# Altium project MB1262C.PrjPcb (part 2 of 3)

## Sheet Peripherals.SchDoc: Peripherals
size A4; Date: 01-DEC-2013; CompanyName: STMicroelectronics; Organization: Microcontrollers Division; Address1: 12, Rue Jules HOROWITZ; Address2: 38019 Grenoble; Address3: FRANCE; DocumentNumber: MB1262; Revision: C-01; SheetNumber: 16; SheetTotal: 17; Project: STM32MP15x-EVAL
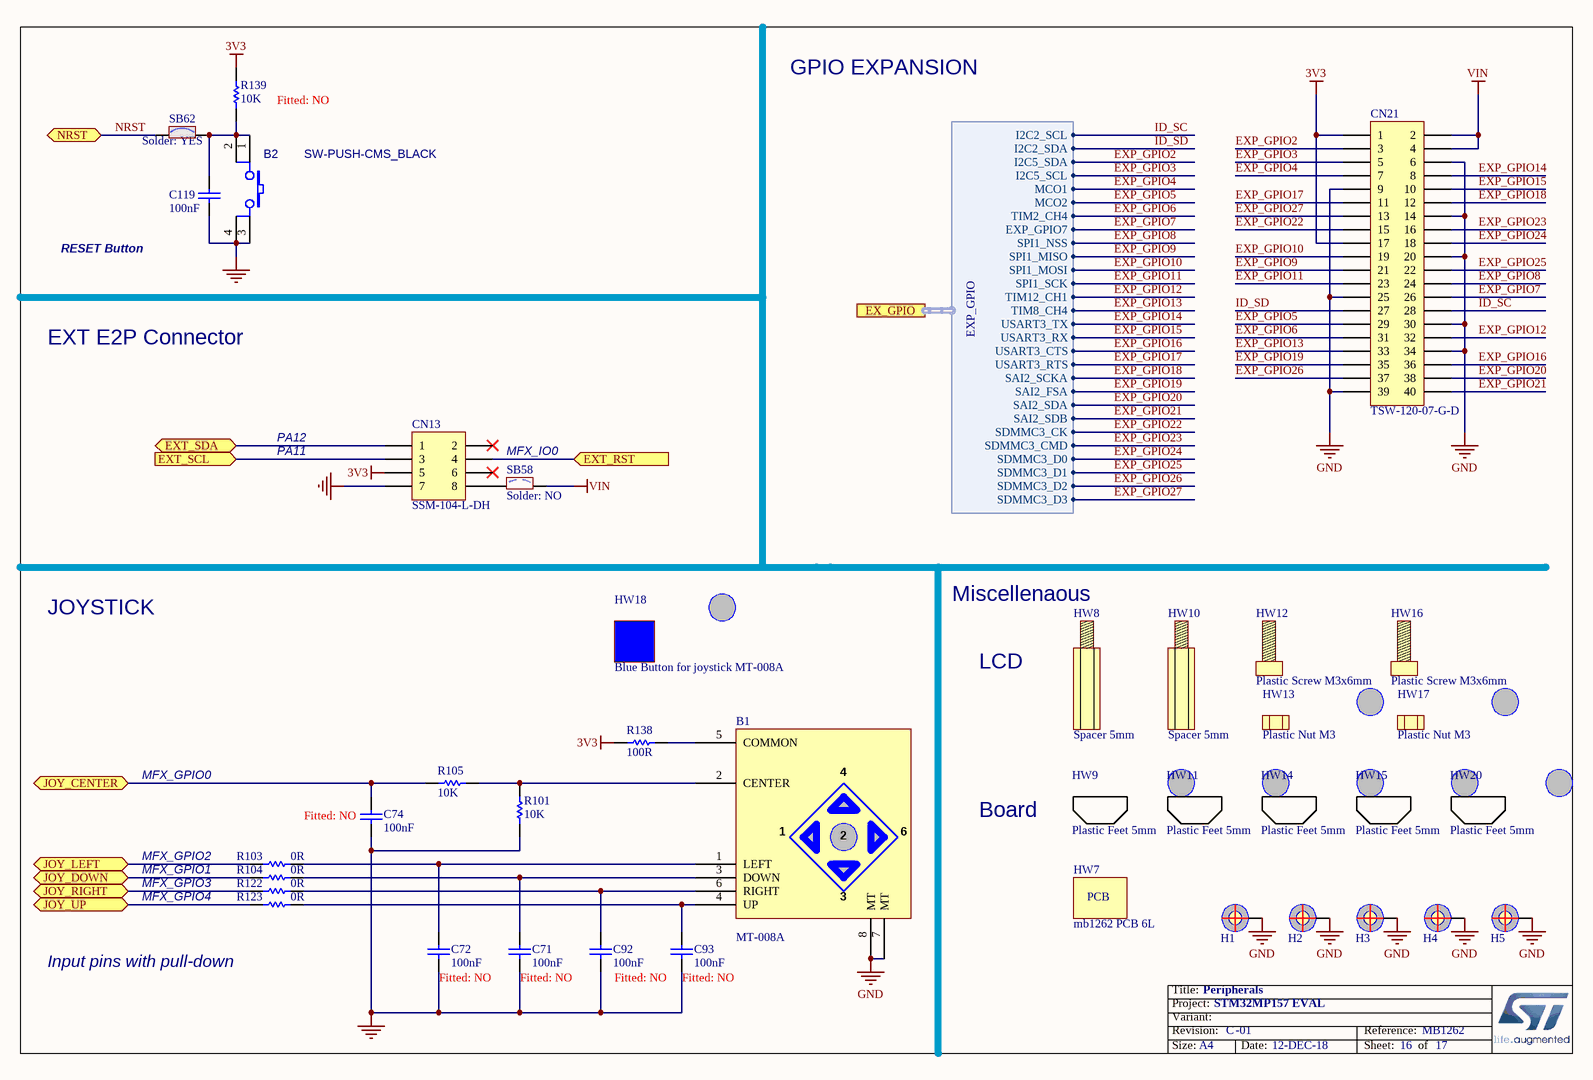
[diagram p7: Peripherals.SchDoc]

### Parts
B1  MT-008A  [SWI_XIEJIA_MT-008A_6P]
B2  SW-PUSH-CMS_BLACK  [SWI_WEALTHMETAL_TD-0341_4P]
C71  100nF  Fitted: NO  [C0402]
C72  100nF  Fitted: NO  [C0402]
C74  100nF  Fitted: NO  [C0402]
C92  100nF  Fitted: NO  [C0402]
C93  100nF  Fitted: NO  [C0402]
C119  100nF  [C0402]
CN13  SSM-104-L-DH  [CON_SAMTEC_SSM-104-L-DH]
CN21  TSW-120-07-G-D  [CON_SAMTEC_TSW-120-07-G-D]
H1  POSITION HOLE C6D3R5  [PTH_M1261-3005-N_3P5X6_M3_H14]  (value not drawn)  (no BOM)
H2  POSITION HOLE C6D3R5  [PTH_M1261-3005-N_3P5X6_M3_H14]  (value not drawn)  (no BOM)
H3  POSITION HOLE C6D3R5  [PTH_M1261-3005-N_3P5X6_M3_H14]  (value not drawn)  (no BOM)
H4  POSITION HOLE C6D3R5  [PTH_M1261-3005-N_3P5X6_M3_H14]  (value not drawn)  (no BOM)
H5  POSITION HOLE C6D3R5  [PTH_M1261-3005-N_3P5X6_M3_H14]  (value not drawn)  (no BOM)
HW7  mb1262 PCB 6L  (mechanical)
HW8  Spacer 5mm  (mechanical)
HW9  Plastic Feet 5mm  (mechanical)
HW10  Spacer 5mm  (mechanical)
HW11  Plastic Feet 5mm  (mechanical)
HW12  Plastic Screw M3x6mm  (mechanical)
HW13  Plastic Nut M3  (mechanical)
HW14  Plastic Feet 5mm  (mechanical)
HW15  Plastic Feet 5mm  (mechanical)
HW16  Plastic Screw M3x6mm  (mechanical)
HW17  Plastic Nut M3  (mechanical)
HW18  Blue Button for joystick MT-008A  (mechanical)
HW20  Plastic Feet 5mm  (mechanical)
R101  10K  [R0402]
R103  0R  [R0402]
R104  0R  [R0402]
R105  10K  [R0402]
R122  0R  [R0402]
R123  0R  [R0402]
R138  100R  [R0402]
R139  10K  Fitted: NO  [R0402]
SB58  Solder: NO  [SOLDER-BRIDGE_R0603-0R]  (hidden comment: SB_OFF)
SB62  Solder: YES  [SOLDER-BRIDGE_R0603-0R]  (hidden comment: SB_ON)

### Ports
EX_GPIO (harness EXP_GPIO), EXT_RST (in), EXT_SCL (in), EXT_SDA (bidir), JOY_CENTER (bidir), JOY_DOWN (bidir), JOY_LEFT (bidir), JOY_RIGHT (bidir), JOY_UP (bidir), NRST (bidir)

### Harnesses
EXP_GPIO: I2C2_SCL, I2C2_SDA, I2C5_SDA, I2C5_SCL, MCO1, MCO2, TIM2_CH4, EXP_GPIO7, SPI1_NSS, SPI1_MISO, SPI1_MOSI, SPI1_SCK, TIM12_CH1, TIM8_CH4, USART3_TX, USART3_RX, USART3_CTS, USART3_RTS, SAI2_SCKA, SAI2_FSA, SAI2_SDA, SAI2_SDB, SDMMC3_CK, SDMMC3_CMD, SDMMC3_D0, SDMMC3_D1, SDMMC3_D2, SDMMC3_D3

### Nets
3V3: CN13.5 CN21.1 CN21.17 R138.1 R139.2
GND: B1.7(MT) B1.8(MT) B2.3 B2.4 C71.1 C72.1 C74.1 C92.1 C93.1 C119.1 CN13.7 CN21.6 CN21.9 CN21.14 CN21.20 CN21.25 CN21.30 CN21.34 CN21.39 H1.1 H2.1 H3.1 H4.1 H5.1 R101.1
VIN: CN21.2 CN21.4 SB58.2
EXP_GPIO2: CN21.3 ; port EX_GPIO.I2C5_SDA
EXP_GPIO3: CN21.5 ; port EX_GPIO.I2C5_SCL
EXP_GPIO4: CN21.7 ; port EX_GPIO.MCO1
EXP_GPIO5: CN21.29 ; port EX_GPIO.MCO2
EXP_GPIO6: CN21.31 ; port EX_GPIO.TIM2_CH4
EXP_GPIO7: CN21.26 ; port EX_GPIO.EXP_GPIO7
EXP_GPIO8: CN21.24 ; port EX_GPIO.SPI1_NSS
EXP_GPIO9: CN21.21 ; port EX_GPIO.SPI1_MISO
EXP_GPIO10: CN21.19 ; port EX_GPIO.SPI1_MOSI
EXP_GPIO11: CN21.23 ; port EX_GPIO.SPI1_SCK
EXP_GPIO12: CN21.32 ; port EX_GPIO.TIM12_CH1
EXP_GPIO13: CN21.33 ; port EX_GPIO.TIM8_CH4
EXP_GPIO14: CN21.8 ; port EX_GPIO.USART3_TX
EXP_GPIO15: CN21.10 ; port EX_GPIO.USART3_RX
EXP_GPIO16: CN21.36 ; port EX_GPIO.USART3_CTS
EXP_GPIO17: CN21.11 ; port EX_GPIO.USART3_RTS
EXP_GPIO18: CN21.12 ; port EX_GPIO.SAI2_SCKA
EXP_GPIO19: CN21.35 ; port EX_GPIO.SAI2_FSA
EXP_GPIO20: CN21.38 ; port EX_GPIO.SAI2_SDA
EXP_GPIO21: CN21.40 ; port EX_GPIO.SAI2_SDB
EXP_GPIO22: CN21.15 ; port EX_GPIO.SDMMC3_CK
EXP_GPIO23: CN21.16 ; port EX_GPIO.SDMMC3_CMD
EXP_GPIO24: CN21.18 ; port EX_GPIO.SDMMC3_D0
EXP_GPIO25: CN21.22 ; port EX_GPIO.SDMMC3_D1
EXP_GPIO26: CN21.37 ; port EX_GPIO.SDMMC3_D2
EXP_GPIO27: CN21.13 ; port EX_GPIO.SDMMC3_D3
ID_SC: CN21.28 ; port EX_GPIO.I2C2_SCL
ID_SD: CN21.27 ; port EX_GPIO.I2C2_SDA
NRST: SB62.1 ; port NRST
NetB1_1: B1.1(LEFT) C72.2 R103.2
NetB1_2: B1.2(CENTER) R101.2 R105.2
NetB1_3: B1.3(DOWN) C71.2 R104.2
NetB1_4: B1.4(UP) C93.2 R123.2
NetB1_5: B1.5(COMMON) R138.2
NetB1_6: B1.6(RIGHT) C92.2 R122.2
NetB2_1: B2.1 B2.2 C119.2 R139.1 SB62.2
NetC74_2: C74.2 R105.1 ; port JOY_CENTER
NetCN13_1: CN13.1 ; port EXT_SDA
NetCN13_3: CN13.3 ; port EXT_SCL
NetCN13_4: CN13.4 ; port EXT_RST
NetCN13_8: CN13.8 SB58.1
NetR103_1: R103.1 ; port JOY_LEFT
NetR104_1: R104.1 ; port JOY_DOWN
NetR122_1: R122.1 ; port JOY_RIGHT
NetR123_1: R123.1 ; port JOY_UP

Not connected (* = marked no-connect by the designer): CN13 2* 6*

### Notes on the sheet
- GPIO EXPANSION
- RESET Button
- EXT E2P Connector
- PA11
- PA12
- MFX_IO0
- (near HW8) Miscellenaous
- JOYSTICK
- LCD
- MFX_GPIO0
- MFX_GPIO1
- MFX_GPIO2
- (near HW9) Board
- MFX_GPIO3
- MFX_GPIO4
- Input pins with pull-down

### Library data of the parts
B1 = MT-008A_M: Joystick with Hat, Multi Function Switch; Manuf_1: XIEJIA Electronics; Ordered_By: Subcon; Fitted: YES
B2 = SW-PUSH-CMS_BLACK: Non-Open Push-Button 0.1A 24V; Manuf_2: FARNELL; Manuf_Part_2: 535-930; Manuf_1: wealthmetal; Manuf_Part_1: TD0341X-G01-BLA; Ref St: 9180120; Ordered_By: Subcon; Fitted: YES
C71 C72 C74 C92 C93 = Cap_100nF_X7R_10%_0402: Capacitor,100nF,16V,X7R,10%,0402,YAGEO; Manuf_Part_1: CC0402KRX7R7BB104; Ordered_By: Subcon
C119 = Cap_100nF_X7R_10%_0402: Capacitor,100nF,16V,X7R,10%,0402,YAGEO; Manuf_Part_1: CC0402KRX7R7BB104; Fitted: YES; Ordered_By: Subcon
CN13 = SSM-104-L-DH: Série SSM, 8 Contact, 2.54 mm, CMS; Manuf_1: SAMTEC; Order_Code: 2097467; Ordered_By: Subcon; Fitted: YES
CN21 = Header 20x2 male: Header,20 pin , Dual Row; Manuf_1: Samtec; Ordered_By: Subcon; Fitted: YES
HW7 = PCB_mb1262: Fitted: YES; Ordered_By: Subcon
HW8 HW10 = Plastic Spacer D5.5*8mm, M3: spacer; Manuf_1: ETTINGER; Order_Code: 1466829; Ordered_By: Subcon; Fitted: YES
HW9 HW11 HW14 HW15 HW20 = Plastic Feet 5mm: Plastic Feet adhesive 5mm; Manuf_1: Multicomp; Manuf_Part_1: PD.2115BL; Ordered_By: Subcon; Order_Code: 1800839; Fitted: YES
HW12 HW16 = Plastic Screw M3x6mm: Plastic screw; Ordered_By: Subcon; Fitted: YES
HW13 HW17 = Plastic Nut M3: Plastic nut; Manuf_1: DURATOOL; Manuf_Part_1: 1110030; Ordered_By: Subcon; Order_Code: 7016943; Fitted: YES; Value: Nut M3
HW18 = Blue Button for joystick MT-008A: Ordered_By: Subcon; Fitted: YES; Value: Blue button MT-008A
R101 R105 = Res_10K_1%_0402: Resistor,10K,0402,1%,YAGEO; Manuf_Part_1: RC0402FR-0710KL; Order_Code: 9239359RL; Fitted: YES; Ordered_By: Subcon
R103 R104 R122 R123 = Res_0_5%_0402: Resistor,0R,0402,5%,YAGEO; Manuf_Part_1: RC0402JR-070RL; Order_Code: 2363467; Fitted: YES; Ordered_By: Subcon
R138 = Res_100_1%_0402: Resistor,100R,0402,1%,YAGEO; Manuf_Part_1: RC0402FR-07100RL; Order_Code: 9239111; Fitted: YES; Ordered_By: Subcon
R139 = Res_10K_1%_0402: Resistor,10K,0402,1%,YAGEO; Manuf_Part_1: RC0402FR-0710KL; Order_Code: 9239359RL; Ordered_By: Subcon
SB58 = SB_OFF: Solder Bridge OFF; Fitted: NO; Ordered_By: Subcon
SB62 = SB_ON: Solder Bridge ON; Ordered_by: Subcon

## Sheet RS232.SchDoc: RS232
size A4; DocumentNumber: MB1262; Revision: C-01; SheetNumber: 10; SheetTotal: 17; Project: STM32MP15x-EVAL
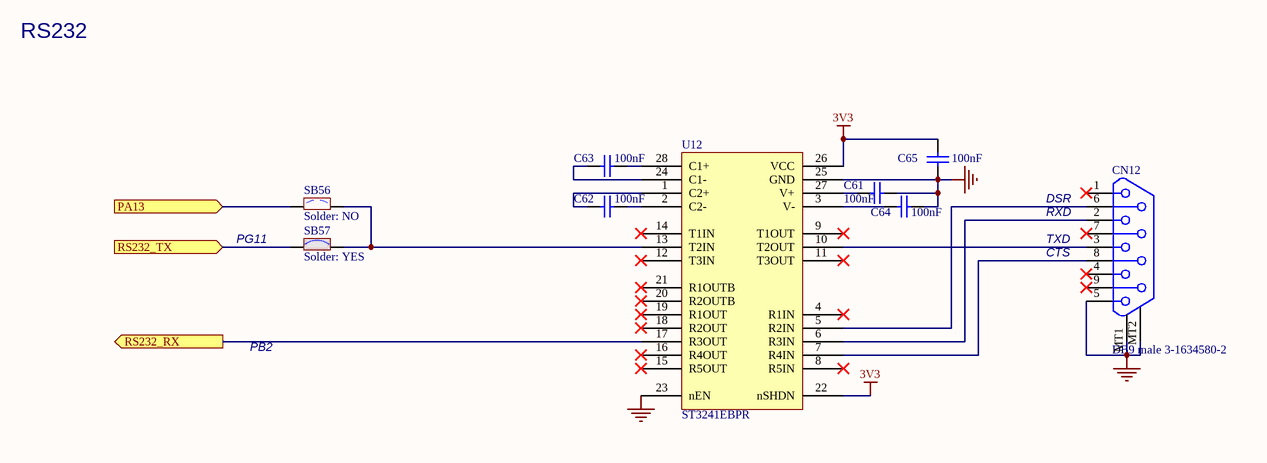
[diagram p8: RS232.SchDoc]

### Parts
C61  100nF  [C0402]
C62  100nF  [C0402]
C63  100nF  [C0402]
C64  100nF  [C0402]
C65  100nF  [C0402]
CN12  DB9 male 3-1634580-2  [CON_DB9-MALE_TYCO_3-1634580-2]
SB56  Solder: NO  [SOLDER-BRIDGE_R0603-0R]  (hidden comment: SB_OFF)
SB57  Solder: YES  [SOLDER-BRIDGE_R0603-0R]  (hidden comment: SB_ON)
U12  ST3241EBPR  [ICC_SSOP28_10P2X5P3_P065]

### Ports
PA13 (in), RS232_RX (out), RS232_TX (in)

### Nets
3V3: C65.1 U12.22(nSHDN) U12.26(VCC)
GND: C61.1 C64.1 C65.2 CN12.5 CN12.MT1 CN12.MT2 U12.23(nEN) U12.25(GND)
PA13: SB56.1 ; port PA13
UART4_RX: U12.17(R3OUT) ; port RS232_RX
UART4_TX: SB57.1 ; port RS232_TX
NetC61_2: C61.2 U12.27(V+)
NetC62_1: C62.1 U12.2(C2-)
NetC62_2: C62.2 U12.1(C2+)
NetC63_1: C63.1 U12.28(C1+)
NetC63_2: C63.2 U12.24(C1-)
NetC64_2: C64.2 U12.3(V-)
NetCN12_2: CN12.2 U12.6(R3IN)
NetCN12_3: CN12.3 U12.10(T2OUT)
NetCN12_6: CN12.6 U12.5(R2IN)
NetCN12_8: CN12.8 U12.7(R4IN)
NetSB56_2: SB56.2 SB57.2 U12.13(T2IN)

Not connected (* = marked no-connect by the designer): CN12 1* 4* 7* 9*; U12 4(R1IN)* 8(R5IN)* 9(T1OUT)* 11(T3OUT)* 12(T3IN)* 14(T1IN)* 15(R5OUT)* 16(R4OUT)* 18(R2OUT)* 19(R1OUT)* 20(R2OUTB)* 21(R1OUTB)*

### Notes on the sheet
- RS232
- PG11
- (near CN12) RXD
- (near CN12) TXD
- (near CN12) DSR
- (near CN12) CTS
- PB2

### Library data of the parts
C61-C65 = Cap_100nF_X7R_10%_0402: as C119 on sheet Peripherals
CN12 = CONN_DB9_male_3_1634580_2: 9 Positions,,through-hole , Right Angle, Product Series = HD 20, With Mating Connector LockMale; Manuf_1: TYCO; Fitted: YES; Ordered_By: Subcon
SB56 = SB_OFF: as SB58 on sheet Peripherals
SB57 = SB_ON: Solder Bridge ON; Ordered_by: Subcon
U12 = ST3241EBPR: RS-232 transceiver with auto-power-down; Manuf_1: ST; Fitted: YES; Ordered_By: Subcon

## Sheet MotorControl.SchDoc: Motor Control
size A4; DocumentNumber: MB1262; Revision: C-01; SheetNumber: 6; SheetTotal: 17; Project: STM32MP15x-EVAL
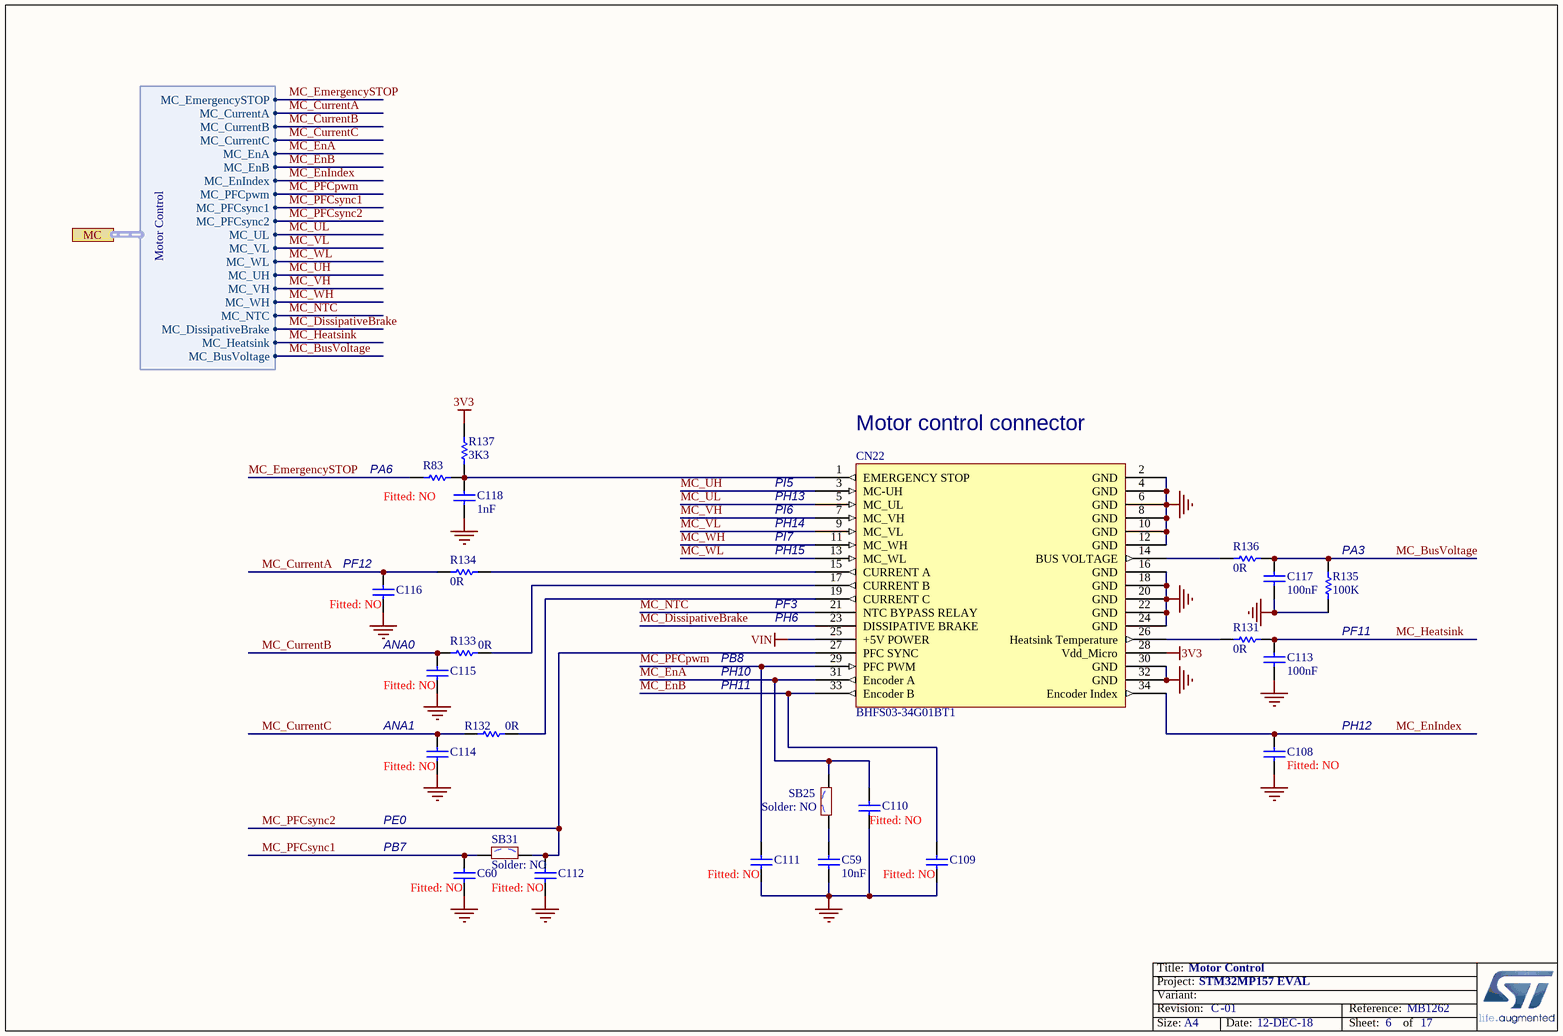
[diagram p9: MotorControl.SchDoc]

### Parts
C59  10nF  [C0402]
C60  Fitted: NO  [C0402]  (hidden comment: 100pF)
C108  Fitted: NO  [C0402]  (hidden comment: 100pF)
C109  Fitted: NO  [C0402]  (hidden comment: 100pF)
C110  Fitted: NO  [C0402]  (hidden comment: 100pF)
C111  Fitted: NO  [C0402]  (hidden comment: 100pF)
C112  Fitted: NO  [C0402]  (hidden comment: 100pF)
C113  100nF  [C0402]
C114  Fitted: NO  [C0402]  (hidden comment: 100pF)
C115  Fitted: NO  [C0402]  (hidden comment: 100pF)
C116  Fitted: NO  [C0402]  (hidden comment: 100pF)
C117  100nF  [C0402]
C118  1nF  [C0402]
CN22  BHFS03-34G01BT1  [CON_SAMTEC_TST-117-01-T-D]
R83  Fitted: NO  [R0402]  (hidden comment: 0R)
R131  0R  [R0402]
R132  0R  [R0402]
R133  0R  [R0402]
R134  0R  [R0402]
R135  100K  [R0402]
R136  0R  [R0402]
R137  3K3  [R0402]
SB25  Solder: NO  [SOLDER-BRIDGE_R0603-0R]  (hidden comment: SB_OFF)
SB31  Solder: NO  [SOLDER-BRIDGE_R0603-0R]  (hidden comment: SB_OFF)

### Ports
MC (harness Motor Control)

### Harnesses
Motor Control: MC_UH, MC_UL, MC_EmergencySTOP, MC_VH, MC_VL, MC_WH, MC_BusVoltage, MC_WL, MC_CurrentA, MC_NTC, MC_DissipativeBrake, MC_Heatsink, MC_CurrentB, MC_PFCpwm, MC_EnA, MC_EnB, MC_EnIndex, MC_CurrentC, MC_PFCsync2, MC_PFCsync1

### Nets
3V3: CN22.28(Vdd_Micro) R137.2
GND: C59.1 C60.1 C108.2 C109.1 C110.1 C111.1 C112.1 C113.1 C114.1 C115.1 C116.1 C117.1 C118.1 CN22.2(GND) CN22.4(GND) CN22.6(GND) CN22.8(GND) CN22.10(GND) CN22.12(GND) CN22.16(GND) CN22.18(GND) CN22.20(GND) CN22.22(GND) CN22.24(GND) CN22.30(GND) CN22.32(GND) R135.1
VIN: CN22.25(+5V_POWER)
MC_BusVoltage: C117.2 R135.2 R136.2 ; port MC.MC_BusVoltage
MC_CurrentA: C116.2 R134.1 ; port MC.MC_CurrentA
MC_CurrentB: C115.2 R133.1 ; port MC.MC_CurrentB
MC_CurrentC: C114.2 R132.1 ; port MC.MC_CurrentC
MC_DissipativeBrake: CN22.23(DISSIPATIVE_BRAKE) ; port MC.MC_DissipativeBrake
MC_EmergencySTOP: R83.1 ; port MC.MC_EmergencySTOP
MC_EnA: C110.2 CN22.31(Encoder_A) SB25.2 ; port MC.MC_EnA
MC_EnB: C109.2 CN22.33(Encoder_B) ; port MC.MC_EnB
MC_EnIndex: C108.1 CN22.34(Encoder_Index) ; port MC.MC_EnIndex
MC_Heatsink: C113.2 R131.2 ; port MC.MC_Heatsink
MC_NTC: CN22.21(NTC_BYPASS_RELAY) ; port MC.MC_NTC
MC_PFCpwm: C111.2 CN22.29(PFC_PWM) ; port MC.MC_PFCpwm
MC_PFCsync1: C60.2 SB31.1 ; port MC.MC_PFCsync1
MC_PFCsync2: C112.2 CN22.27(PFC_SYNC) SB31.2 ; port MC.MC_PFCsync2
MC_UH: CN22.3(MC-UH) ; port MC.MC_UH
MC_UL: CN22.5(MC_UL) ; port MC.MC_UL
MC_VH: CN22.7(MC_VH) ; port MC.MC_VH
MC_VL: CN22.9(MC_VL) ; port MC.MC_VL
MC_WH: CN22.11(MC_WH) ; port MC.MC_WH
MC_WL: CN22.13(MC_WL) ; port MC.MC_WL
NetC59_2: C59.2 SB25.1
NetC118_2: C118.2 CN22.1(EMERGENCY_STOP) R83.2 R137.1
NetCN22_14: CN22.14(BUS_VOLTAGE) R136.1
NetCN22_15: CN22.15(CURRENT_A) R134.2
NetCN22_17: CN22.17(CURRENT_B) R133.2
NetCN22_19: CN22.19(CURRENT_C) R132.2
NetCN22_26: CN22.26(Heatsink_Temperature) R131.1

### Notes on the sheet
- (near CN22) Motor control connector
- (near R83) PA6
- PH13
- PI5
- PI6
- (near C116) PF12
- PH14
- PH15
- PI7
- (near R135) PA3
- ANA0
- PF3
- PH6
- (near R135) PF11
- PH11
- PH10
- PB8
- ANA1
- PH12
- PB7
- PE0

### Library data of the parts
C59 = Cap_10nF_X7R_10%_0402_1: Capacitor,10nF,16V,X7R,10%,0402,YAGEO; Manuf_Part_1: CC0402KRX7R7BB103; Fitted: YES; Ordered_By: Subcon
C60 C108-C112 C114-C116 = Cap_100pF_NPO_5%_0402: Capacitor,100pF,50V,NPO,5%,0402,YAGEO; Order_Code: CC0402JRNPO9BN101; Ordered_By: Subcon
C113 C117 = Cap_100nF_X7R_10%_0402: as C119 on sheet Peripherals
C118 = Cap_1nF_X7R_10%_0402: Capacitor,1nF,16V,X7R,10%,0402,YAGEO; Manuf_Part_1: CC0402KRX7R7BB102; Order_Code: 1816754; Fitted: YES; Ordered_By: Subcon
CN22 = MotorControl_connector: Motor Control connector WINPIN; Fitted: YES; Ordered_By: Subcon
R83 = Res_0_5%_0402: Resistor,0R,0402,5%,YAGEO; Manuf_Part_1: RC0402JR-070RL; Order_Code: 2363467; Ordered_By: Subcon
R131-R134 R136 = Res_0_5%_0402: as R103 on sheet Peripherals
R135 = Res_100K_1%_0402: Resistor,100K,0402,1%,YAGEO; Manuf_Part_2: RT0402FRE07100KL; Manuf_Part_1: RC0402FR-07100KL; Fitted: YES; Ordered_By: Subcon
R137 = Res_3K3_1%_0402: Resistor,3K3,0402,1%,YAGEO; Manuf_Part_1: RC0402FR-073K3L; Order_Code: 9239294RL; Fitted: YES; Ordered_By: Subcon
SB25 SB31 = SB_OFF: as SB58 on sheet Peripherals

## Sheet CAN_FD&TT.SchDoc: CAN FD&TT
size A4; DocumentNumber: MB1262; Revision: C-01; SheetNumber: 7; SheetTotal: 17; Project: STM32MP15x-EVAL
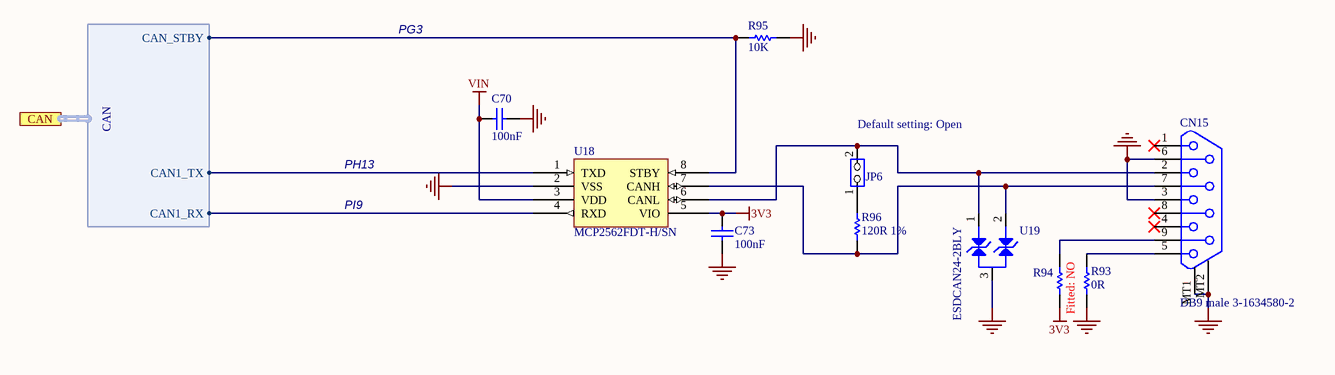
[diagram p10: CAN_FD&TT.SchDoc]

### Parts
C70  100nF  [C0402]
C73  100nF  [C0402]
CN15  DB9 male 3-1634580-2  [CON_DB9-MALE_TYCO_3-1634580-2]
JP6  Jumper_2.54mm  [CON_SAMTEC_TSW-102-07-G-S]  (value not drawn)
R93  0R  [R0402]
R94  Fitted: NO  [R0402]  (hidden comment: 1K)
R95  10K  [R0402]
R96  120R 1%  [R0402]
U18  MCP2562FDT-H/SN  [ICC_SO8_5X4_P127]
U19  ESDCAN24-2BLY  [ESD_SOT23]

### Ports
CAN (harness CAN)

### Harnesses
CAN: CAN1_TX, CAN1_RX, CAN_STBY

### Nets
3V3: C73.2 R94.1 U18.5(VIO)
GND: C70.1 C73.1 CN15.3 CN15.6 CN15.MT1 CN15.MT2 R93.1 R95.2 U18.2(VSS) U19.3
VIN: C70.2 U18.3(VDD)
CAN1_RX: U18.4(RXD) ; port CAN.CAN1_RX
CAN1_TX: U18.1(TXD) ; port CAN.CAN1_TX
CAN_STBY: R95.1 U18.8(STBY) ; port CAN.CAN_STBY
NetCN15_2: CN15.2 JP6.2(NO) U18.6(CANL) U19.1
NetCN15_5: CN15.5 R93.2
NetCN15_7: CN15.7 R96.1 U18.7(CANH) U19.2
NetCN15_9: CN15.9 R94.2
NetJP6_1: JP6.1(COMMON) R96.2

Not connected (* = marked no-connect by the designer): CN15 1* 4* 8*

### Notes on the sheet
- PG3
- (near JP6) Default setting: Open
- PH13
- PI9

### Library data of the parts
C70 C73 = Cap_100nF_X7R_10%_0402: as C119 on sheet Peripherals
CN15 = CONN_DB9_male_3_1634580_2: as CN12 on sheet RS232
JP6 = TSW-102-07-x-S: Connector jumper 1 position; Manuf_1: SAMTEC; Manuf_Part_2: 4711955140470; Manuf_2: KONTEC; Order_Code: 423-2841; Fitted: YES; Ordered_By: Subcon
R93 = Res_0_5%_0402: as R103 on sheet Peripherals
R94 = Res_1K_1%_0402: Resistor,1K,0402,1%,YAGEO; Manuf_Part_1: RC0402FR-071KL; Ordered_By: Subcon
R95 = Res_10K_1%_0402: as R101 on sheet Peripherals
R96 = Res_120_1%_0402: Resistor,120R,0402,1%,YAGEO; Manuf_Part_1: RC0402FR-07120RL; Order_Code: 9239120RL; Fitted: YES; Ordered_By: Subcon
U18 = MCP2562FD: High-Speed CAN Flexible Data Rate Transceiver; Manuf_1: Microchip; Fitted: YES; Ordered_By: Subcon
U19 = ESDCAN24-2BLY: transient voltage suppressor for ESD protection for CAN bus; Manuf_1: ST; Fitted: YES; Ordered_By: Subcon

## Sheet JTAG&Trace.SchDoc: JTAG & Trace
size A4; DocumentNumber: MB1262; Revision: C-01; SheetNumber: 9; SheetTotal: 17; Project: STM32MP15x-EVAL
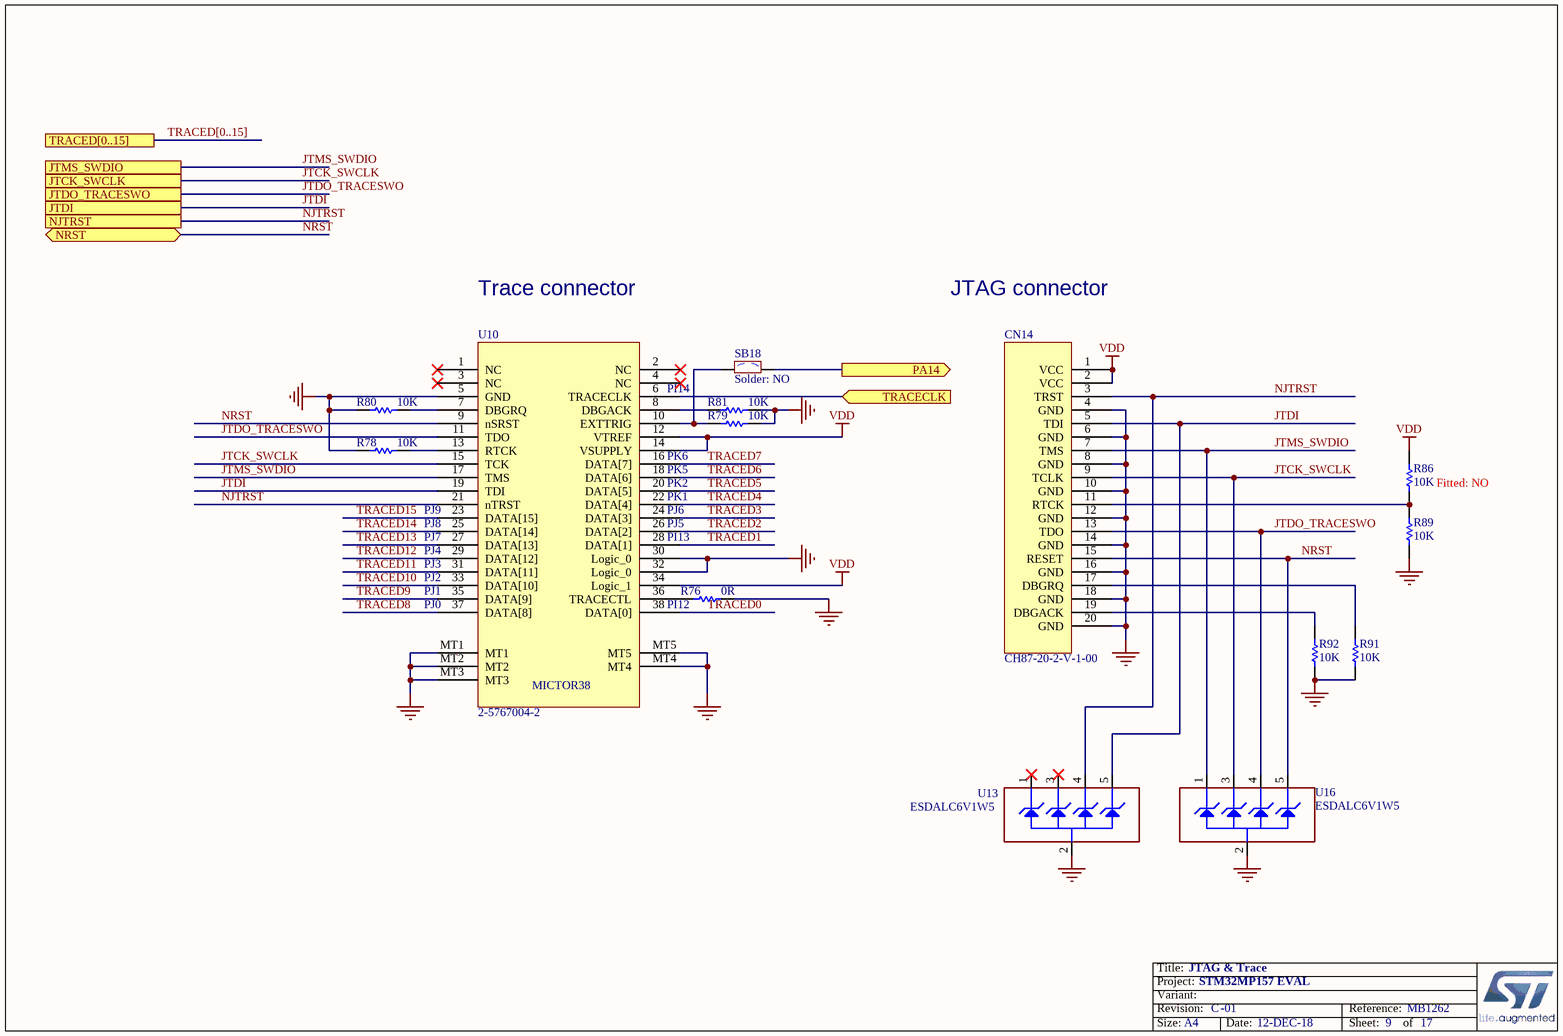
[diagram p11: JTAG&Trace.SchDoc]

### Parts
CN14  CH87-20-2-V-1-00  [CON_CVILUX_CH87-20-2-V-1-00]
R76  0R  [R0402]
R78  10K  [R0402]
R79  10K  [R0402]
R80  10K  [R0402]
R81  10K  [R0402]
R86  10K  Fitted: NO  [R0402]
R89  10K  [R0402]
R91  10K  [R0402]
R92  10K  [R0402]
SB18  Solder: NO  [SOLDER-BRIDGE_R0603-0R]  (hidden comment: SB_OFF)
U10  2-5767004-2  [CON_MICTOR_TYCO_2-5767004-2]
U13  ESDALC6V1W5  [ESD_SOT323-5L]
U16  ESDALC6V1W5  [ESD_SOT323-5L]

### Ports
JTCK_SWCLK, JTDI, JTDO_TRACESWO, JTMS_SWDIO, NJTRST, NRST (bidir), PA14 (out), TRACECLK (in), TRACED[0..15]

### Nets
GND: CN14.4(GND) CN14.6(GND) CN14.8(GND) CN14.10(GND) CN14.12(GND) CN14.14(GND) CN14.16(GND) CN14.18(GND) CN14.20(GND) R76.2 R78.2 R79.1 R80.2 R81.1 R89.1 R91.1 R92.1 U10.5(GND) U10.30(Logic_0) U10.32(Logic_0) U10.MT1 U10.MT2 U10.MT3 U10.MT4 U10.MT5 U13.2(GND) U16.2(GND)
VDD: CN14.1(VCC) CN14.2(VCC) R86.2 U10.12(VTREF) U10.14(VSUPPLY) U10.34(Logic_1)
JTCK_SWCLK: CN14.9(TCLK) U10.15(TCK) U16.3(IO2) ; port JTCK_SWCLK
JTDI: CN14.5(TDI) U10.19(TDI) U13.5(IO4) ; port JTDI
JTDO_TRACESWO: CN14.13(TDO) U10.11(TDO) U16.4(IO3) ; port JTDO_TRACESWO
JTMS_SWDIO: CN14.7(TMS) U10.17(TMS) U16.1(IO1) ; port JTMS_SWDIO
NJTRST: CN14.3(TRST) U10.21(nTRST) U13.4(IO3) ; port NJTRST
NRST: CN14.15(RESET) U10.9(nSRST) U16.5(IO4) ; port NRST
PA14: SB18.2 ; port PA14
TRACED0: U10.38(DATA[0])
TRACED1: U10.28(DATA[1])
TRACED2: U10.26(DATA[2])
TRACED3: U10.24(DATA[3])
TRACED4: U10.22(DATA[4])
TRACED5: U10.20(DATA[5])
TRACED6: U10.18(DATA[6])
TRACED7: U10.16(DATA[7])
TRACED8: U10.37(DATA[8])
TRACED9: U10.35(DATA[9])
TRACED10: U10.33(DATA[10])
TRACED11: U10.31(DATA[11])
TRACED12: U10.29(DATA[12])
TRACED13: U10.27(DATA[13])
TRACED14: U10.25(DATA[14])
TRACED15: U10.23(DATA[15])
NetCN14_11: CN14.11(RTCK) R86.1 R89.2
NetCN14_17: CN14.17(DBGRQ) R91.2
NetCN14_19: CN14.19(DBGACK) R92.2
NetR76_1: R76.1 U10.36(TRACECTL)
NetR78_1: R78.1 U10.13(RTCK)
NetR79_2: R79.2 SB18.1 U10.10(EXTTRIG)
NetR80_1: R80.1 U10.7(DBGRQ)
NetR81_2: R81.2 U10.8(DBGACK)
NetSB38_2: U10.6(TRACECLK) ; port TRACECLK

Not connected (* = marked no-connect by the designer): U10 1(NC)* 2(NC)* 3(NC)* 4(NC)*; U13 1(IO1)* 3(IO2)*

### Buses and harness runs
bus TRACED[0..15] = port TRACED[0..15]

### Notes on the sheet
- Trace connector
- JTAG connector
- PI14
- (near U10) PJ9
- (near U10) PJ6
- (near U10) PK1
- (near U10) PK2
- (near U10) PK5
- (near U10) PK6
- (near U10) PJ8
- (near U10) PJ7
- (near U10) PJ4
- (near U10) PJ3
- (near U10) PJ2
- (near U10) PI13
- (near U10) PJ5
- (near U10) PJ1
- (near U10) PJ0
- (near R76) PI12

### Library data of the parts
CN14 = CONN_Header_2x10_Male_JTAG: Headers 2x10pins CH87 series 2.54mm Male; Manuf_1: CVILUX; Fitted: YES; Ordered_By: Subcon
R76 = Res_0_5%_0402: as R103 on sheet Peripherals
R78-R81 R89 R91 R92 = Res_10K_1%_0402: as R101 on sheet Peripherals
R86 = Res_10K_1%_0402: as R139 on sheet Peripherals
SB18 = SB_OFF: as SB58 on sheet Peripherals
U10 = CONN_Mictor_38_SMT: Mictor 38 pins Vertical Receptacles 2-5767004-2; Manuf_1: TYCO; Fitted: YES; Ordered_By: Subcon
U13 U16 = ESDALC6V1W5: Dual Transil array for ESD protection; Manuf_1: STM; Manuf_Part_1: ESDA5V3L; Ref St: 9179034; Provided: ST; ECCN_US/EU: EAR99/NEC; Ordered_By: Subcon; Fitted: YES

## Sheet QSPI.SchDoc: QSPI
size A4; CompanyName: STMicroelectronics; DocumentNumber: MB1262; Revision: B-01; SheetNumber: 5; SheetTotal: 17; Project: STM32MP15x-EVAL
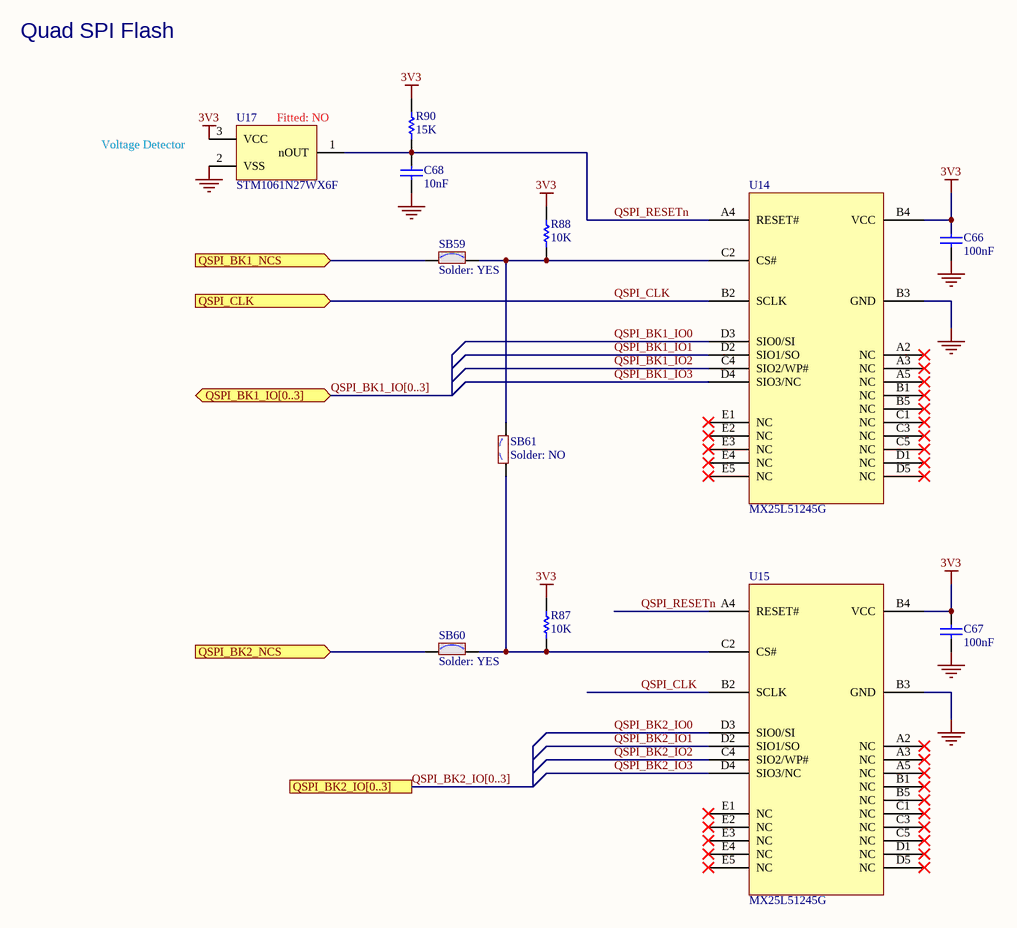
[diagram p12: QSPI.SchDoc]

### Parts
C66  100nF  [C0402]
C67  100nF  [C0402]
C68  10nF  [C0402]
R87  10K  [R0402]
R88  10K  [R0402]
R90  15K  [R0402]
SB59  Solder: YES  [SOLDER-BRIDGE_R0603-0R]  (hidden comment: SB_ON)
SB60  Solder: YES  [SOLDER-BRIDGE_R0603-0R]  (hidden comment: SB_ON)
SB61  Solder: NO  [SOLDER-BRIDGE_R0603-0R]  (hidden comment: SB_OFF)
U14  MX25L51245G  [ICC_BGA24_5X5-BALL-ARRAY_6X8_P1]
U15  MX25L51245G  [ICC_BGA24_5X5-BALL-ARRAY_6X8_P1]
U17  Fitted: NO  [REG_SOT23]  (hidden comment: STM1061N27WX6F)

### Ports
QSPI_BK1_IO[0..3] (bidir), QSPI_BK1_NCS (in), QSPI_BK2_IO[0..3], QSPI_BK2_NCS (in), QSPI_CLK (in)

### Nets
3V3: C66.2 C67.2 R87.2 R88.2 R90.1 U14.B4(VCC) U15.B4(VCC) U17.3(VCC)
GND: C66.1 C67.1 C68.1 U14.B3(GND) U15.B3(GND) U17.2(VSS)
QSPI_BK1_IO0: U14.D3(SIO0/SI)
QSPI_BK1_IO1: U14.D2(SIO1/SO)
QSPI_BK1_IO2: U14.C4(SIO2/WP#)
QSPI_BK1_IO3: U14.D4(SIO3/NC)
QSPI_BK1_NCS: SB59.1 ; port QSPI_BK1_NCS
QSPI_BK2_IO0: U15.D3(SIO0/SI)
QSPI_BK2_IO1: U15.D2(SIO1/SO)
QSPI_BK2_IO2: U15.C4(SIO2/WP#)
QSPI_BK2_IO3: U15.D4(SIO3/NC)
QSPI_BK2_NCS: SB60.1 ; port QSPI_BK2_NCS
QSPI_CLK: U14.B2(SCLK) U15.B2(SCLK) ; port QSPI_CLK
QSPI_RESETn: C68.2 R90.2 U14.A4(RESET#) U15.A4(RESET#) U17.1(nOUT)
NetR87_1: R87.1 SB60.2 SB61.1 U15.C2(CS#)
NetR88_1: R88.1 SB59.2 SB61.2 U14.C2(CS#)

Not connected (* = marked no-connect by the designer): U14 A2(NC)* A3(NC)* A5(NC)* B1(NC)* B5(NC)* C1(NC)* C3(NC)* C5(NC)* D1(NC)* D5(NC)* E1(NC)* E2(NC)* E3(NC)* E4(NC)* E5(NC)*; U15 A2(NC)* A3(NC)* A5(NC)* B1(NC)* B5(NC)* C1(NC)* C3(NC)* C5(NC)* D1(NC)* D5(NC)* E1(NC)* E2(NC)* E3(NC)* E4(NC)* E5(NC)*

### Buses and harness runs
bus QSPI_BK1_IO[0..3] = port QSPI_BK1_IO[0..3]
bus QSPI_BK2_IO[0..3] = port QSPI_BK2_IO[0..3]

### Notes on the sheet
- Quad SPI Flash
- (near U17) Voltage Detector

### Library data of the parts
C66 C67 = Cap_100nF_X7R_10%_0402: as C119 on sheet Peripherals
C68 = Cap_10nF_X7R_10%_0402: Capacitor,10nF,16V,X7R,10%,0402,YAGEO; Manuf_Part_1: CC0402KRX7R7BB103; Fitted: YES; Ordered_By: Subcon
R87 R88 = Res_10K_1%_0402: as R101 on sheet Peripherals
R90 = Res_15K_5%_0402: Resistor,15K,0402,5%,1/16W; Manufacturer_Part_Number: RC0402JR-0715KL; Manufacturer: YAGEO; Ordered_By: Subcon; Fitted: YES
SB59 SB60 = SB_ON: Solder Bridge ON; Ordered_by: Subcon
SB61 = SB_OFF: as SB58 on sheet Peripherals
U14 U15 = MX25L51245G: Serial NOR 512Mb/3V BGA; Manuf_Part_1: MX25L51245G-XD; Manuf_1: MACRONIX; Fitted: YES; Ordered_By: STM
U17 = STM1061_WX: Low power Voltage Detector 2.7V Open Drain; Part_Type: IC; Manuf_1: STMICROELECTRONICS; Initial_Board_Reference: MB1262C; Remark: schematics symbol updated to fit SOT23 pinning; Ordered_By: Subcon

## Sheet MFX.SchDoc: MFX
size A4; DocumentNumber: MB1262; Revision: C-01; SheetNumber: 17; SheetTotal: 17; Project: STM32MP15x-EVAL
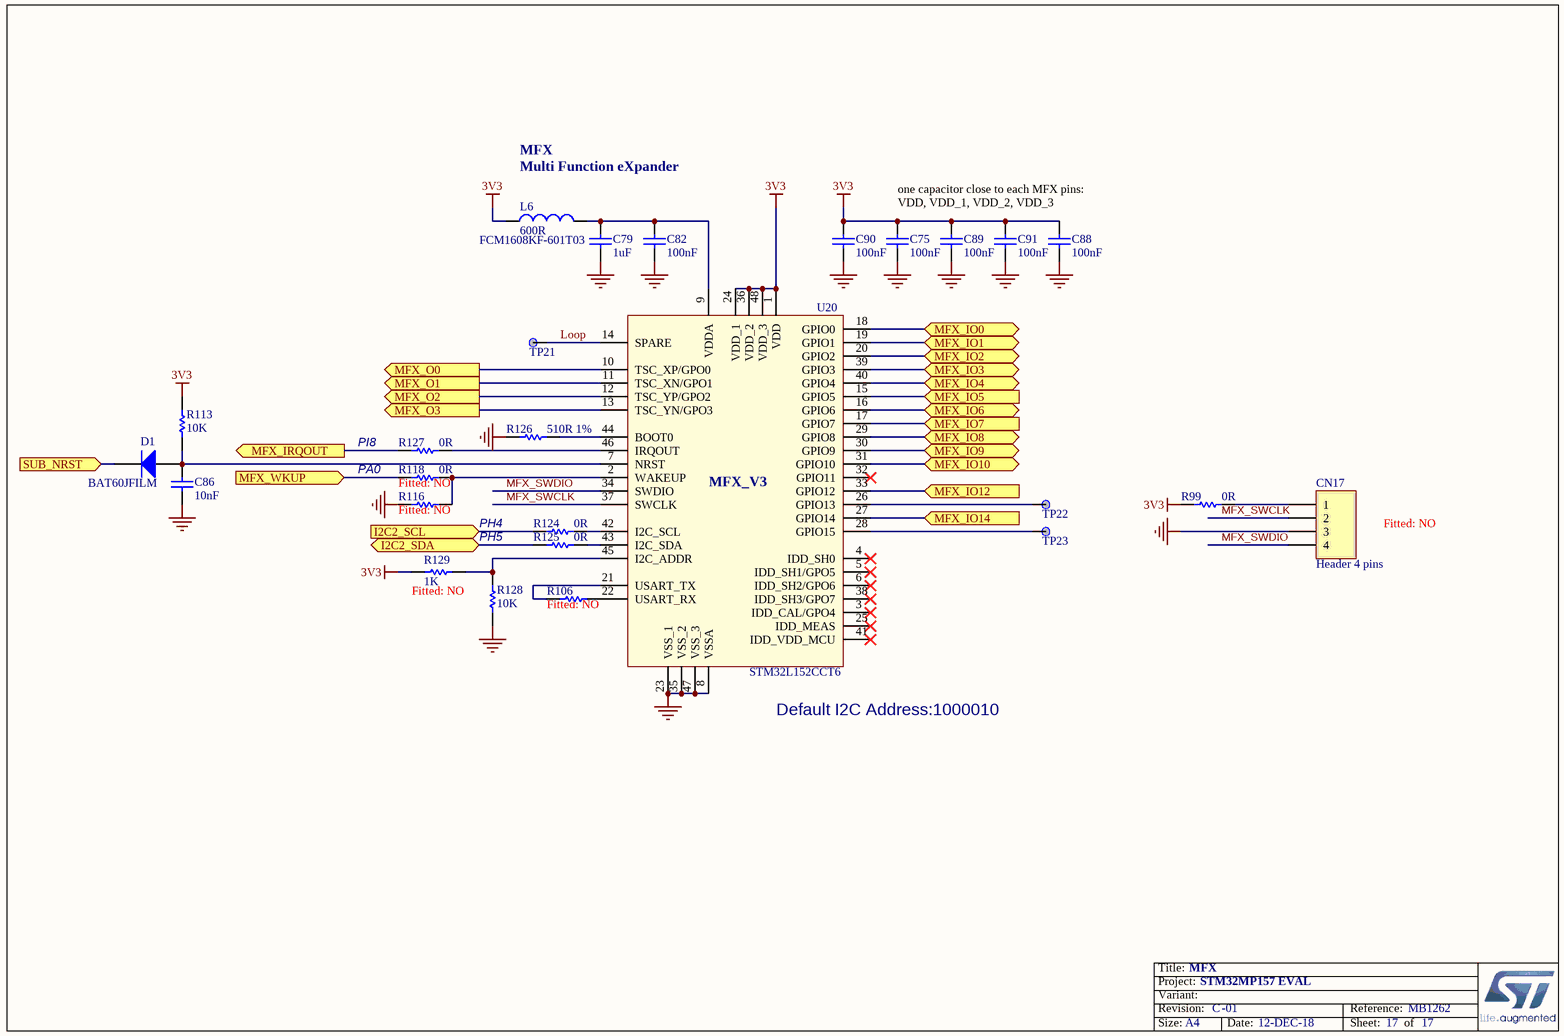
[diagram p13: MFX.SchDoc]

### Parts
C75  100nF  [C0402]
C79  1uF  [C0402]
C82  100nF  [C0402]
C86  10nF  [C0402]
C88  100nF  [C0402]
C89  100nF  [C0402]
C90  100nF  [C0402]
C91  100nF  [C0402]
CN17  Header 4 pins  Fitted: NO  [CON_SAMTEC_TSW-104-07-G-S]
D1  BAT60JFILM  [DIO_SOD323]
L6  600R  Manuf_Part_1: FCM1608KF-601T03  [L0603]
R99  0R  [R0402]
R106  Fitted: NO  [R0402]  (hidden comment: 100R 1%)
R113  10K  [R0402]
R116  Fitted: NO  [R0402]  (hidden comment: 47K)
R118  0R  Fitted: NO  [R0402]
R124  0R  [R0402]
R125  0R  [R0402]
R126  510R 1%  [R0402]
R127  0R  [R0402]
R128  10K  [R0402]
R129  1K  Fitted: NO  [R0402]
TP21  TP  [TP_SMD_1MM]  (value not drawn)
TP22  TP  [TP_SMD_1MM]  (value not drawn)
TP23  TP  [TP_SMD_1MM]  (value not drawn)
U20  STM32L152CCT6  [ICC_LQFP48_7X7_P050]

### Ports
I2C2_SCL (in), I2C2_SDA (bidir), MFX_IO0 (bidir), MFX_IO1 (bidir), MFX_IO2 (bidir), MFX_IO3 (bidir), MFX_IO4 (bidir), MFX_IO5 (in), MFX_IO6 (bidir), MFX_IO7 (in), MFX_IO8 (bidir), MFX_IO9 (bidir), MFX_IO10 (bidir), MFX_IO12 (in), MFX_IO14 (in), MFX_IRQOUT (out), MFX_O0 (out), MFX_O1 (out), MFX_O2 (out), MFX_O3 (out), MFX_WKUP (in), SUB_NRST (in)

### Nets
3V3: C75.2 C88.2 C89.2 C90.2 C91.2 L6.1 R99.2 R113.2 R129.2 U20.1(VDD) U20.24(VDD_1) U20.36(VDD_2) U20.48(VDD_3)
GND: C75.1 C79.1 C82.1 C86.1 C88.1 C89.1 C90.1 C91.1 CN17.3 R116.1 R126.1 R128.1 U20.8(VSSA) U20.23(VSS_1) U20.35(VSS_2) U20.47(VSS_3)
Anti_TAMP2: R127.1 ; port MFX_IRQOUT
HDMI_PD: U20.11(TSC_XN/GPO1) ; port MFX_O1
I2C2_SCL: R124.1 ; port I2C2_SCL
I2C2_SDA: R125.1 ; port I2C2_SDA
LCD_INT: U20.27(GPIO14) ; port MFX_IO14
Loop: TP21.1 U20.14(SPARE)
MFX_SWCLK: CN17.2 U20.37(SWCLK)
MFX_SWDIO: CN17.4 U20.34(SWDIO)
MIC_MEMS_LED: U20.31(GPIO10) ; port MFX_IO10
PA0_WKUP: R118.1 ; port MFX_WKUP
NetC74_2: U20.18(GPIO0) ; port MFX_IO0
NetC79_2: C79.2 C82.2 L6.2 U20.9(VDDA)
NetC86_2: C86.2 D1.1(A) R113.1 U20.7(NRST)
NetCN7_15: U20.33(GPIO12) ; port MFX_IO12
NetCN7_17: U20.13(TSC_YN/GPO3) ; port MFX_O3
NetCN7_19: U20.12(TSC_YP/GPO2) ; port MFX_O2
NetCN10_26: D1.2(K) ; port SUB_NRST
NetCN13_4: U20.10(TSC_XP/GPO0) ; port MFX_O0
NetCN17_1: CN17.1 R99.1
NetR5_2: U20.16(GPIO6) ; port MFX_IO6
NetR22_1: U20.30(GPIO9) ; port MFX_IO9
NetR23_1: U20.29(GPIO8) ; port MFX_IO8
NetR24_2: U20.17(GPIO7) ; port MFX_IO7
NetR103_1: U20.20(GPIO2) ; port MFX_IO2
NetR104_1: U20.19(GPIO1) ; port MFX_IO1
NetR106_1: R106.1 U20.21(USART_TX)
NetR106_2: R106.2 U20.22(USART_RX)
NetR116_2: R116.2 R118.2 U20.2(WAKEUP)
NetR122_1: U20.39(GPIO3) ; port MFX_IO3
NetR123_1: U20.40(GPIO4) ; port MFX_IO4
NetR124_2: R124.2 U20.42(I2C_SCL)
NetR125_2: R125.2 U20.43(I2C_SDA)
NetR126_2: R126.2 U20.44(BOOT0)
NetR127_2: R127.2 U20.46(IRQOUT)
NetR128_2: R128.2 R129.1 U20.45(I2C_ADDR)
NetTP22_1: TP22.1 U20.26(GPIO13)
NetTP23_1: TP23.1 U20.28(GPIO15)
NetU8_G3: U20.15(GPIO5) ; port MFX_IO5

Not connected (* = marked no-connect by the designer): U20 3(IDD_CAL/GPO4)* 4(IDD_SH0)* 5(IDD_SH1/GPO5)* 6(IDD_SH2/GPO6)* 25(IDD_MEAS)* 32(GPIO11)* 38(IDD_SH3/GPO7)* 41(IDD_VDD_MCU)*

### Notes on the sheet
- MFX
  Multi Function eXpander
- one capacitor close to each MFX pins: VDD, VDD_1, VDD_2, VDD_3
- PI8
- PA0
- PH4
- PH5
- (near U20) Default I2C Address:1000010

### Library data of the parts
C75 C82 C88-C91 = Cap_100nF_X7R_10%_0402: as C119 on sheet Peripherals
C79 = Cap_1uF_X5R_10%_6V3_0402: Capacitor MLCC 1µF 10% 6,3V 0,4uF@3,3V X5R 0402 MURATA; Manuf_Part_1: GRM155R60J105KE19; Fitted: YES; Ordered_By: Subcon
C86 = Cap_10nF_X7R_10%_0402: as C68 on sheet QSPI
CN17 = Header 4: Header, 4-Pin; Manuf_1: Samtec; Manuf_Part_1: TSW-104-07-x-S; Ordered_By: Subcon
D1 = BAT60JFILM: Manuf_1: STM; Ordered_By: Subcon; ECCN_US/EU: EAR99/NEC; Ref St: 9151097; Fitted: YES
L6 = BEAD_600R_350MA_0603: Bead,600R,350mA,0603; Manuf_2: TDK; Manuf_Part_2: MPZ1608S300A; Manuf_1: Tai-tech; Manuf_Part_3: BLM18PG121SN1D; Manuf_3: MURATA; Ordered_By: Subcon; Fitted: YES
R99 R124 R125 R127 = Res_0_5%_0402: as R103 on sheet Peripherals
R106 = Res_100_1%_0402: Resistor,100R,0402,1%,YAGEO; Manuf_Part_1: RC0402FR-07100RL; Order_Code: 9239111; Ordered_By: Subcon
R113 R128 = Res_10K_1%_0402: as R101 on sheet Peripherals
R116 = Res_47K_1%_0402: Resistor,47K,0402,1%,YAGEO; Manuf_Part_1: RC0402FR-0747KL; Order_Code: 9239430; Ordered_By: Subcon
R118 = Res_0_5%_0402: as R83 on sheet MotorControl
R126 = Res_510_1%_0402: Resistor,510R,0402,1%,YAGEO; Manuf_Part_1: RC0402FR-07510RL; Order_Code: 1458804; Fitted: YES; Ordered_By: Subcon
R129 = Res_1K_1%_0402: as R94 on sheet CAN_FD&TT
TP21-TP23 = TP 1mm: Test Point; Fitted: YES; Ordered_By: Subcon
U20 = STM32L152CCT6: Multifunction expander; Manuf_1: ST; Fitted: YES; Order_Code: 2333393; Ordered_By: Subcon

## Sheet Samtec Connectors QSH_North_South.SchDoc: Daughter Board Connectors
size A3; Date: 01-DEC-2013; CompanyName: STMicroelectronics; Organization: Microcontrollers Division; Address1: 12, Rue Jules HOROWITZ; Address2: 38019 Grenoble; Address3: FRANCE; DocumentNumber: MB1262; Revision: C-01; SheetNumber: 3; SheetTotal: 17; Project: STM32MP15x-EVAL; PageSetup: Record=PageOptions¦CenterHorizontal=True¦CenterVertical=True¦PrintScale=1.00¦XCorrection=1.00¦YCorrection=1.00¦PrintKind=1¦BorderSize=5000000¦LeftOffset=0¦BottomOffset=0¦Orientation=2¦PaperLength=1000¦PaperWidth=1000¦Scale=100¦PaperSource=7¦PrintQuality=-3¦MediaType=1¦DitherType=10¦PrintScaleMode=1¦PaperKind=A3¦PaperIndex=8
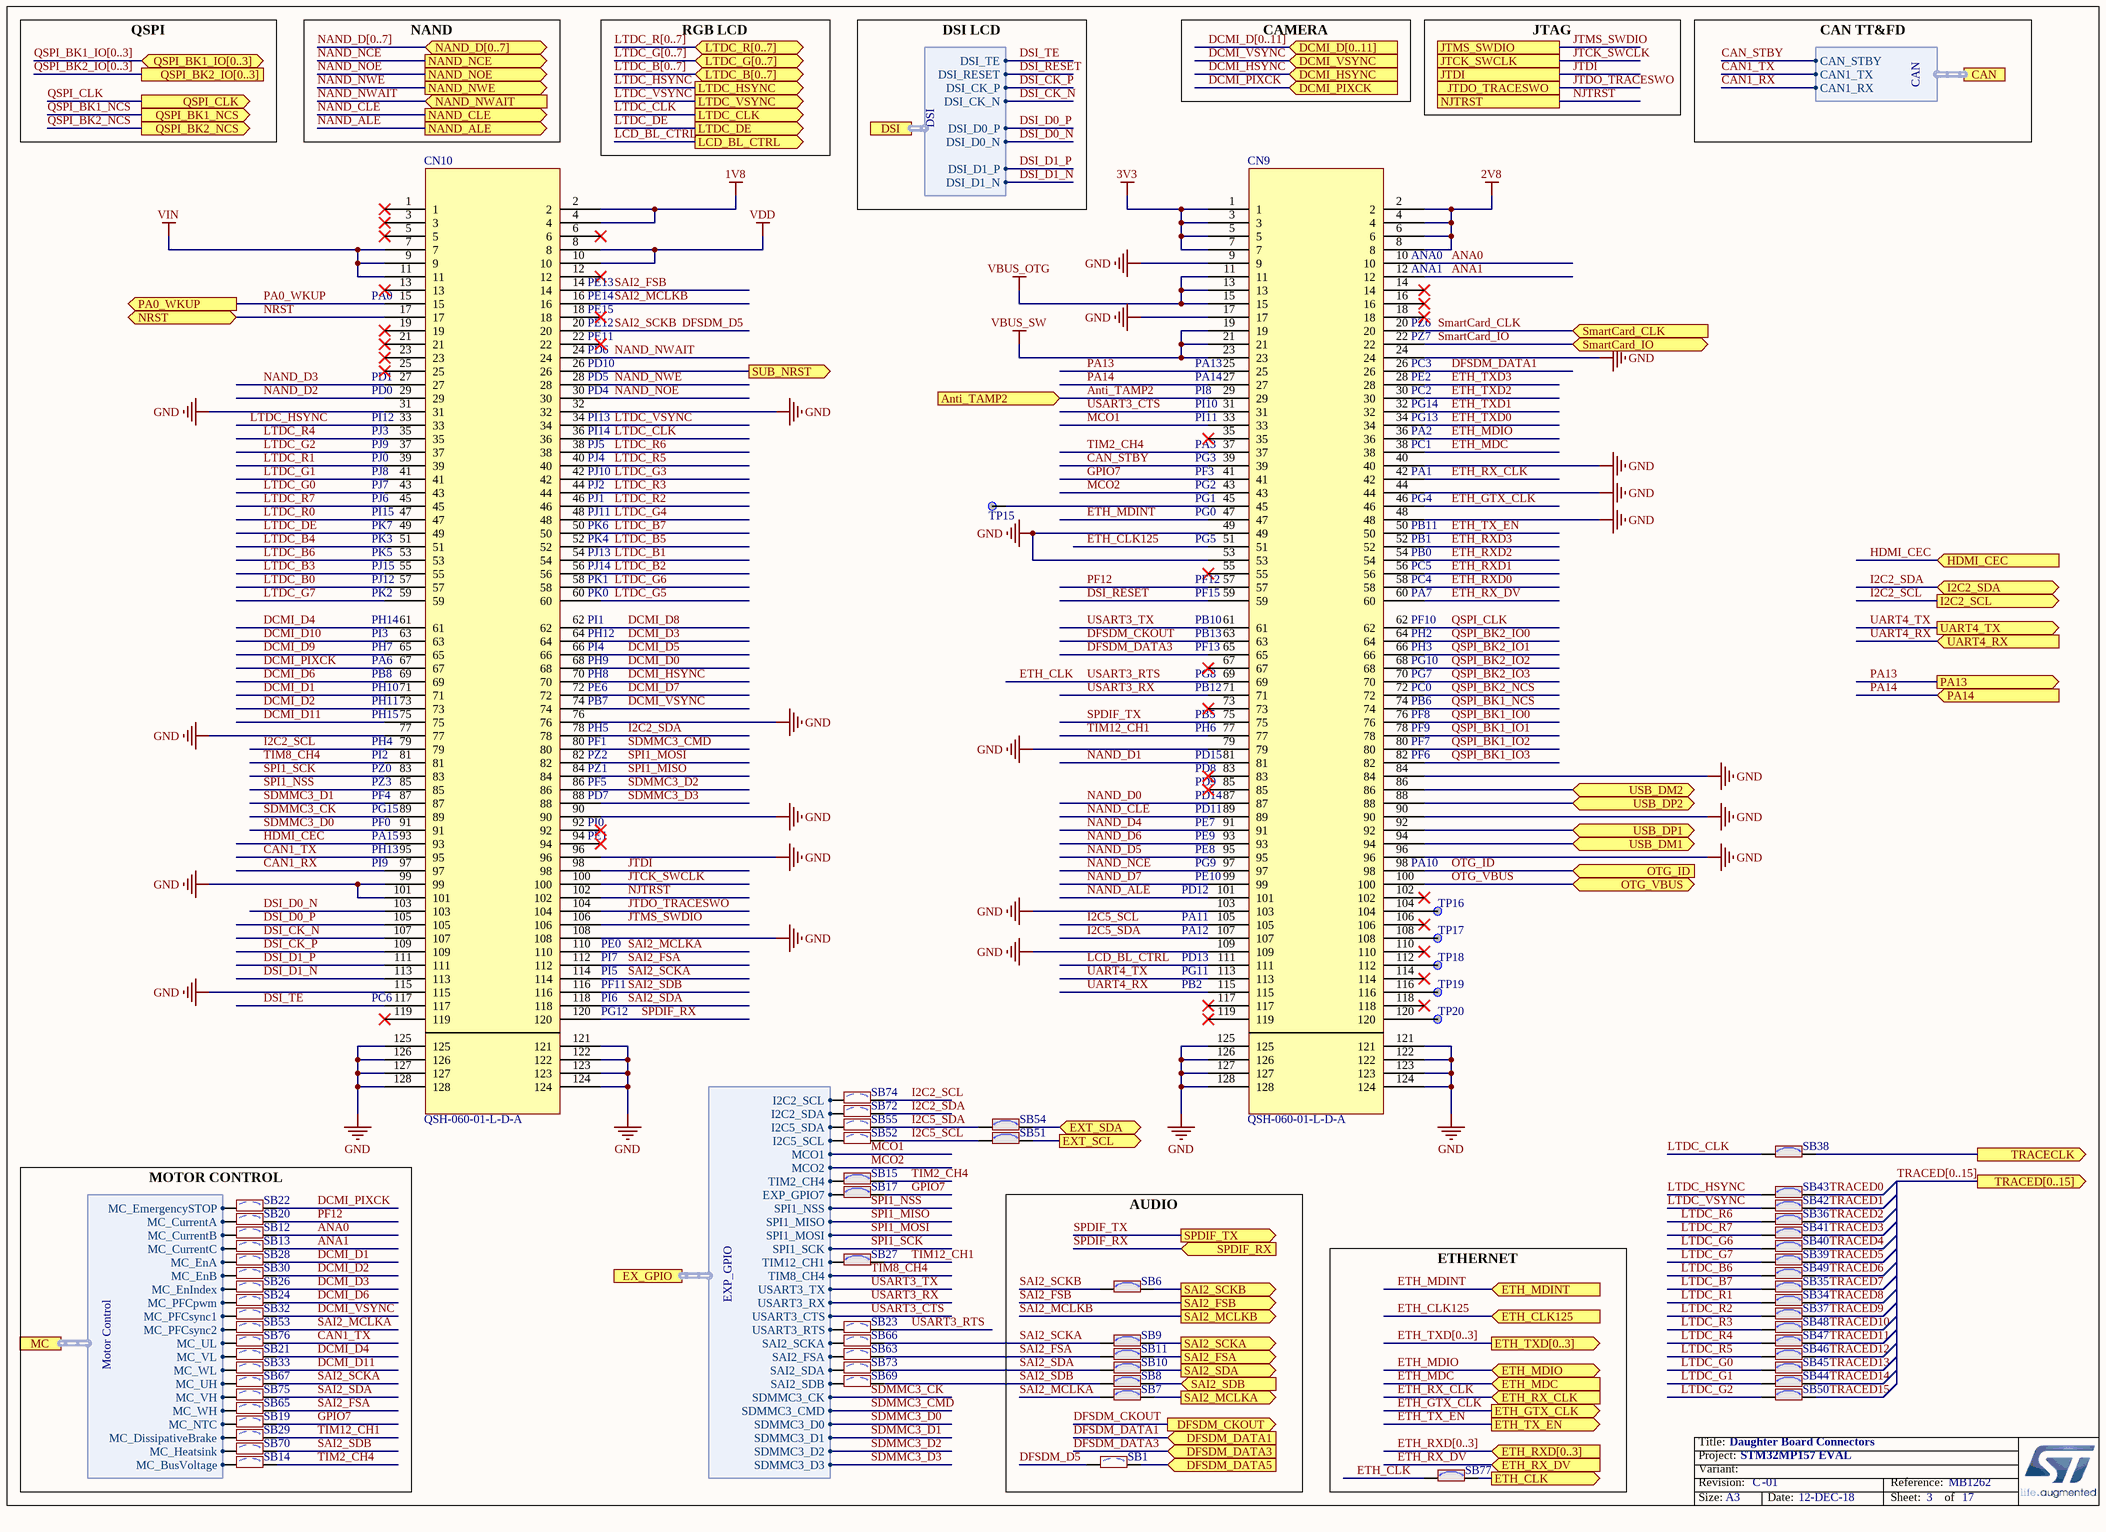
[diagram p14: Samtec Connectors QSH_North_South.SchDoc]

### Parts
CN9  QSH-060-01-L-D-A  [CON_SAMTEC_QSH-060-01-L-D-A]
CN10  QSH-060-01-L-D-A  [CON_SAMTEC_QSH-060-01-L-D-A]
SB1  SB_OFF  [SOLDER-BRIDGE_R0603-0R]  (value not drawn)
SB6  SB_ON  [SOLDER-BRIDGE_R0603-0R]  (value not drawn)
SB7  SB_ON  [SOLDER-BRIDGE_R0603-0R]  (value not drawn)
SB8  SB_ON  [SOLDER-BRIDGE_R0603-0R]  (value not drawn)
SB9  SB_ON  [SOLDER-BRIDGE_R0603-0R]  (value not drawn)
SB10  SB_ON  [SOLDER-BRIDGE_R0603-0R]  (value not drawn)
SB11  SB_ON  [SOLDER-BRIDGE_R0603-0R]  (value not drawn)
SB12  SB_OFF  [SOLDER-BRIDGE_R0603-0R]  (value not drawn)
SB13  SB_OFF  [SOLDER-BRIDGE_R0603-0R]  (value not drawn)
SB14  SB_OFF  [SOLDER-BRIDGE_R0603-0R]  (value not drawn)
SB15  SB_ON  [SOLDER-BRIDGE_R0603-0R]  (value not drawn)
SB17  SB_ON  [SOLDER-BRIDGE_R0603-0R]  (value not drawn)
SB19  SB_OFF  [SOLDER-BRIDGE_R0603-0R]  (value not drawn)
SB20  SB_OFF  [SOLDER-BRIDGE_R0603-0R]  (value not drawn)
SB21  SB_OFF  [SOLDER-BRIDGE_R0603-0R]  (value not drawn)
SB22  SB_OFF  [SOLDER-BRIDGE_R0603-0R]  (value not drawn)
SB23  SB_OFF  [SOLDER-BRIDGE_R0603-0R]  (value not drawn)
SB24  SB_OFF  [SOLDER-BRIDGE_R0603-0R]  (value not drawn)
SB26  SB_OFF  [SOLDER-BRIDGE_R0603-0R]  (value not drawn)
SB27  SB_ON  [SOLDER-BRIDGE_R0603-0R]  (value not drawn)
SB28  SB_OFF  [SOLDER-BRIDGE_R0603-0R]  (value not drawn)
SB29  SB_OFF  [SOLDER-BRIDGE_R0603-0R]  (value not drawn)
SB30  SB_OFF  [SOLDER-BRIDGE_R0603-0R]  (value not drawn)
SB32  SB_OFF  [SOLDER-BRIDGE_R0603-0R]  (value not drawn)
SB33  SB_OFF  [SOLDER-BRIDGE_R0603-0R]  (value not drawn)
SB34  SB_ON  [SOLDER-BRIDGE_R0603-0R]  (value not drawn)
SB35  SB_ON  [SOLDER-BRIDGE_R0603-0R]  (value not drawn)
SB36  SB_ON  [SOLDER-BRIDGE_R0603-0R]  (value not drawn)
SB37  SB_ON  [SOLDER-BRIDGE_R0603-0R]  (value not drawn)
SB38  SB_ON  [SOLDER-BRIDGE_R0603-0R]  (value not drawn)
SB39  SB_ON  [SOLDER-BRIDGE_R0603-0R]  (value not drawn)
SB40  SB_ON  [SOLDER-BRIDGE_R0603-0R]  (value not drawn)
SB41  SB_ON  [SOLDER-BRIDGE_R0603-0R]  (value not drawn)
SB42  SB_ON  [SOLDER-BRIDGE_R0603-0R]  (value not drawn)
SB43  SB_ON  [SOLDER-BRIDGE_R0603-0R]  (value not drawn)
SB44  SB_ON  [SOLDER-BRIDGE_R0603-0R]  (value not drawn)
SB45  SB_ON  [SOLDER-BRIDGE_R0603-0R]  (value not drawn)
SB46  SB_ON  [SOLDER-BRIDGE_R0603-0R]  (value not drawn)
SB47  SB_ON  [SOLDER-BRIDGE_R0603-0R]  (value not drawn)
SB48  SB_ON  [SOLDER-BRIDGE_R0603-0R]  (value not drawn)
SB49  SB_ON  [SOLDER-BRIDGE_R0603-0R]  (value not drawn)
SB50  SB_ON  [SOLDER-BRIDGE_R0603-0R]  (value not drawn)
SB51  SB_ON  [SOLDER-BRIDGE_R0603-0R]  (value not drawn)
SB52  SB_OFF  [SOLDER-BRIDGE_R0603-0R]  (value not drawn)
SB53  SB_OFF  [SOLDER-BRIDGE_R0603-0R]  (value not drawn)
SB54  SB_ON  [SOLDER-BRIDGE_R0603-0R]  (value not drawn)
SB55  SB_OFF  [SOLDER-BRIDGE_R0603-0R]  (value not drawn)
SB63  SB_OFF  [SOLDER-BRIDGE_R0603-0R]  (value not drawn)
SB65  SB_OFF  [SOLDER-BRIDGE_R0603-0R]  (value not drawn)
SB66  SB_OFF  [SOLDER-BRIDGE_R0603-0R]  (value not drawn)
SB67  SB_OFF  [SOLDER-BRIDGE_R0603-0R]  (value not drawn)
SB69  SB_OFF  [SOLDER-BRIDGE_R0603-0R]  (value not drawn)
SB70  SB_OFF  [SOLDER-BRIDGE_R0603-0R]  (value not drawn)
SB72  SB_OFF  [SOLDER-BRIDGE_R0603-0R]  (value not drawn)
SB73  SB_OFF  [SOLDER-BRIDGE_R0603-0R]  (value not drawn)
SB74  SB_OFF  [SOLDER-BRIDGE_R0603-0R]  (value not drawn)
SB75  SB_OFF  [SOLDER-BRIDGE_R0603-0R]  (value not drawn)
SB76  SB_OFF  [SOLDER-BRIDGE_R0603-0R]  (value not drawn)
SB77  SB_ON  [SOLDER-BRIDGE_R0603-0R]  (value not drawn)
TP15  TP  [TP_SMD_1MM]  (value not drawn)
TP16  TP  [TP_SMD_1MM]  (value not drawn)
TP17  TP  [TP_SMD_1MM]  (value not drawn)
TP18  TP  [TP_SMD_1MM]  (value not drawn)
TP19  TP  [TP_SMD_1MM]  (value not drawn)
TP20  TP  [TP_SMD_1MM]  (value not drawn)

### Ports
Anti_TAMP2 (in), CAN (harness CAN), DCMI_D[0..11] (in), DCMI_HSYNC (in), DCMI_PIXCK (in), DCMI_VSYNC (in), DFSDM_CKOUT (out), DFSDM_DATA1 (in), DFSDM_DATA3 (in), DFSDM_DATA5 (in), DSI (harness DSI), ETH_CLK125 (in), ETH_CLK (out), ETH_GTX_CLK (out), ETH_MDC (in), ETH_MDINT (in), ETH_MDIO (bidir), ETH_RX_CLK (in), ETH_RX_DV (in), ETH_RXD[0..3] (in), ETH_TX_EN (out), ETH_TXD[0..3] (out), EX_GPIO (harness EXP_GPIO), EXT_SCL (out), EXT_SDA (bidir), HDMI_CEC (in), I2C2_SCL (out), I2C2_SDA (bidir), JTCK_SWCLK, JTDI, JTDO_TRACESWO, JTMS_SWDIO, LCD_BL_CTRL (out), LTDC_B[0..7] (bidir), LTDC_CLK (out), LTDC_DE (out), LTDC_G[0..7] (bidir), LTDC_HSYNC (out), LTDC_R[0..7] (bidir), LTDC_VSYNC (out), MC (harness Motor Control), NAND_ALE (out), NAND_CLE (out), NAND_D[0..7] (bidir), NAND_NCE (out), NAND_NOE (out), NAND_NWAIT (in), NAND_NWE (out), NJTRST, NRST (bidir), OTG_ID (in), OTG_VBUS (bidir), PA0_WKUP (out), PA13 (out), PA14 (in), QSPI_BK1_IO[0..3] (bidir), QSPI_BK1_NCS (out), QSPI_BK2_IO[0..3], QSPI_BK2_NCS (out), QSPI_CLK (out), SAI2_FSA (out), SAI2_FSB (out), SAI2_MCLKA (out), SAI2_MCLKB (out), SAI2_SCKA (out), SAI2_SCKB (out), SAI2_SDA (out), SAI2_SDB (in), SmartCard_CLK (in), SmartCard_IO (bidir), SPDIF_RX (in), SPDIF_TX (out), SUB_NRST (out), TRACECLK (out), TRACED[0..15] (out), UART4_RX (in), UART4_TX (out), USB_DM1 (bidir), USB_DM2 (bidir), USB_DP1 (bidir), USB_DP2 (bidir)

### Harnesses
EXP_GPIO: I2C2_SCL, I2C2_SDA, I2C5_SDA, I2C5_SCL, MCO1, MCO2, TIM2_CH4, EXP_GPIO7, SPI1_NSS, SPI1_MISO, SPI1_MOSI, SPI1_SCK, TIM12_CH1, TIM8_CH4, USART3_TX, USART3_RX, USART3_CTS, USART3_RTS, SAI2_SCKA, SAI2_FSA, SAI2_SDA, SAI2_SDB, SDMMC3_CK, SDMMC3_CMD, SDMMC3_D0, SDMMC3_D1, SDMMC3_D2, SDMMC3_D3
Motor Control: MC_UH, MC_UL, MC_EmergencySTOP, MC_VH, MC_VL, MC_WH, MC_BusVoltage, MC_WL, MC_CurrentA, MC_NTC, MC_DissipativeBrake, MC_Heatsink, MC_CurrentB, MC_PFCpwm, MC_EnA, MC_EnB, MC_EnIndex, MC_CurrentC, MC_PFCsync2, MC_PFCsync1
DSI: DSI_CK_P, DSI_CK_N, DSI_D0_P, DSI_D0_N, DSI_D1_P, DSI_D1_N, DSI_TE, DSI_RESET
CAN: CAN1_TX, CAN1_RX, CAN_STBY

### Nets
1V8: CN10.2 CN10.4
2V8: CN9.2 CN9.4 CN9.6 CN9.8
3V3: CN9.1 CN9.3 CN9.5 CN9.7
GND: CN9.9 CN9.17 CN9.24 CN9.40 CN9.44 CN9.48 CN9.49 CN9.53 CN9.79 CN9.84 CN9.90 CN9.96 CN9.103 CN9.109 CN9.121 CN9.122 CN9.123 CN9.124 CN9.125 CN9.126 CN9.127 CN9.128 CN10.31 CN10.32 CN10.76 CN10.77 CN10.90 CN10.96 CN10.99 CN10.101 CN10.108 CN10.115 CN10.121 CN10.122 CN10.123 CN10.124 CN10.125 CN10.126 CN10.127 CN10.128
VBUS_OTG: CN9.11 CN9.13 CN9.15
VBUS_SW: CN9.19 CN9.21 CN9.23
VDD: CN10.8 CN10.10
VIN: CN10.7 CN10.9 CN10.11
ANA0: CN9.10 SB12.2
ANA1: CN9.12 SB13.2
Anti_TAMP2: CN9.29 ; port Anti_TAMP2
CAN1_RX: CN10.97 ; port CAN.CAN1_RX
CAN1_TX: CN10.95 SB76.2 ; port CAN.CAN1_TX
CAN_STBY: CN9.39 ; port CAN.CAN_STBY
DCMI_D0: CN10.68
DCMI_D1: CN10.71 SB28.2
DCMI_D2: CN10.73 SB30.2
DCMI_D3: CN10.64 SB26.2
DCMI_D4: CN10.61 SB21.2
DCMI_D5: CN10.66
DCMI_D6: CN10.69 SB24.2
DCMI_D7: CN10.72
DCMI_D8: CN10.62
DCMI_D9: CN10.65
DCMI_D10: CN10.63
DCMI_D11: CN10.75 SB33.2
DCMI_HSYNC: CN10.70 ; port DCMI_HSYNC
DCMI_PIXCK: CN10.67 SB22.2 ; port DCMI_PIXCK
DCMI_VSYNC: CN10.74 SB32.2 ; port DCMI_VSYNC
DFSDM_CKOUT: CN9.63 ; port DFSDM_CKOUT
DFSDM_D5: CN10.20 SB1.1 SB6.1  [also labelled SAI2_SCKB]
DFSDM_DATA1: CN9.26 ; port DFSDM_DATA1
DFSDM_DATA3: CN9.65 ; port DFSDM_DATA3
DFSDM_DATA5: SB1.2 ; port DFSDM_DATA5
DSI_CK_N: CN10.107 ; port DSI.DSI_CK_N
DSI_CK_P: CN10.109 ; port DSI.DSI_CK_P
DSI_D0_N: CN10.103 ; port DSI.DSI_D0_N
DSI_D0_P: CN10.105 ; port DSI.DSI_D0_P
DSI_D1_N: CN10.113 ; port DSI.DSI_D1_N
DSI_D1_P: CN10.111 ; port DSI.DSI_D1_P
DSI_RESET: CN9.59 ; port DSI.DSI_RESET
DSI_TE: CN10.117 ; port DSI.DSI_TE
ETH_CLK: CN9.69 SB23.2 SB77.1  [also labelled USART3_RTS]
ETH_CLK125: CN9.51 ; port ETH_CLK125  [project net CLK125]
ETH_GTX_CLK: CN9.46 ; port ETH_GTX_CLK
ETH_MDC: CN9.38 ; port ETH_MDC
ETH_MDINT: CN9.47 ; port ETH_MDINT
ETH_MDIO: CN9.36 ; port ETH_MDIO
ETH_RX_CLK: CN9.42 ; port ETH_RX_CLK
ETH_RX_DV: CN9.60 ; port ETH_RX_DV
ETH_RXD0: CN9.58
ETH_RXD1: CN9.56
ETH_RXD2: CN9.54
ETH_RXD3: CN9.52
ETH_TX_EN: CN9.50 ; port ETH_TX_EN
ETH_TXD0: CN9.34
ETH_TXD1: CN9.32
ETH_TXD2: CN9.30
ETH_TXD3: CN9.28
EXP_GPIO2: SB55.1 ; port EX_GPIO.I2C5_SDA
EXP_GPIO3: SB52.1 ; port EX_GPIO.I2C5_SCL
EXP_GPIO6: SB15.1 ; port EX_GPIO.TIM2_CH4
EXP_GPIO7: SB17.1 ; port EX_GPIO.EXP_GPIO7
EXP_GPIO12: SB27.1 ; port EX_GPIO.TIM12_CH1
EXP_GPIO17: SB23.1 ; port EX_GPIO.USART3_RTS
EXP_GPIO18: SB66.1 ; port EX_GPIO.SAI2_SCKA
EXP_GPIO19: SB63.1 ; port EX_GPIO.SAI2_FSA
EXP_GPIO20: SB73.1 ; port EX_GPIO.SAI2_SDA
EXP_GPIO21: SB69.1 ; port EX_GPIO.SAI2_SDB
GPIO7: CN9.41 SB17.2 SB19.2
HDMI_CEC: CN10.93 ; port HDMI_CEC
I2C2_SCL: CN10.79 SB74.2 ; port I2C2_SCL
I2C2_SDA: CN10.78 SB72.2 ; port I2C2_SDA
I2C5_SCL: CN9.105 SB51.1 SB52.2
I2C5_SDA: CN9.107 SB54.1 SB55.2
ID_SC: SB74.1 ; port EX_GPIO.I2C2_SCL
ID_SD: SB72.1 ; port EX_GPIO.I2C2_SDA
JTCK_SWCLK: CN10.100 ; port JTCK_SWCLK
JTDI: CN10.98 ; port JTDI
JTDO_TRACESWO: CN10.104 ; port JTDO_TRACESWO
JTMS_SWDIO: CN10.106 ; port JTMS_SWDIO
LCD_BL_CTRL: CN9.111 ; port LCD_BL_CTRL
LTDC_B0: CN10.57
LTDC_B1: CN10.54
LTDC_B2: CN10.56
LTDC_B3: CN10.55
LTDC_B4: CN10.51
LTDC_B5: CN10.52
LTDC_B6: CN10.53 SB49.1
LTDC_B7: CN10.50 SB35.1
LTDC_CLK: CN10.36 SB38.1 ; port LTDC_CLK
LTDC_DE: CN10.49 ; port LTDC_DE
LTDC_G0: CN10.43 SB45.1
LTDC_G1: CN10.41 SB44.1
LTDC_G2: CN10.37 SB50.1
LTDC_G3: CN10.42
LTDC_G4: CN10.48
LTDC_G5: CN10.60
LTDC_G6: CN10.58 SB40.1
LTDC_G7: CN10.59 SB39.1
LTDC_HSYNC: CN10.33 SB43.1 ; port LTDC_HSYNC
LTDC_R0: CN10.47
LTDC_R1: CN10.39 SB34.1
LTDC_R2: CN10.46 SB37.1
LTDC_R3: CN10.44 SB48.1
LTDC_R4: CN10.35 SB47.1
LTDC_R5: CN10.40 SB46.1
LTDC_R6: CN10.38 SB36.1
LTDC_R7: CN10.45 SB41.1
LTDC_VSYNC: CN10.34 SB42.1 ; port LTDC_VSYNC
MC_BusVoltage: SB14.1 ; port MC.MC_BusVoltage
MC_CurrentA: SB20.1 ; port MC.MC_CurrentA
MC_CurrentB: SB12.1 ; port MC.MC_CurrentB
MC_CurrentC: SB13.1 ; port MC.MC_CurrentC
MC_DissipativeBrake: SB29.1 ; port MC.MC_DissipativeBrake
MC_EmergencySTOP: SB22.1 ; port MC.MC_EmergencySTOP
MC_EnA: SB28.1 ; port MC.MC_EnA
MC_EnB: SB30.1 ; port MC.MC_EnB
MC_EnIndex: SB26.1 ; port MC.MC_EnIndex
MC_Heatsink: SB70.1 ; port MC.MC_Heatsink
MC_NTC: SB19.1 ; port MC.MC_NTC
MC_PFCpwm: SB24.1 ; port MC.MC_PFCpwm
MC_PFCsync1: SB32.1 ; port MC.MC_PFCsync1
MC_PFCsync2: SB53.1 ; port MC.MC_PFCsync2
MC_UH: SB67.1 ; port MC.MC_UH
MC_UL: SB76.1 ; port MC.MC_UL
MC_VH: SB75.1 ; port MC.MC_VH
MC_VL: SB21.1 ; port MC.MC_VL
MC_WH: SB65.1 ; port MC.MC_WH
MC_WL: SB33.1 ; port MC.MC_WL
MCO1: CN9.33 ; port EX_GPIO.MCO1  [project net EXP_GPIO4]
MCO2: CN9.43 ; port EX_GPIO.MCO2  [project net EXP_GPIO5]
NAND_ALE: CN9.101 ; port NAND_ALE
NAND_CLE: CN9.89 ; port NAND_CLE
NAND_D0: CN9.87
NAND_D1: CN9.81
NAND_D2: CN10.29
NAND_D3: CN10.27
NAND_D4: CN9.91
NAND_D5: CN9.95
NAND_D6: CN9.93
NAND_D7: CN9.99
NAND_NCE: CN9.97 ; port NAND_NCE
NAND_NOE: CN10.30 ; port NAND_NOE
NAND_NWAIT: CN10.24 ; port NAND_NWAIT
NAND_NWE: CN10.28 ; port NAND_NWE
NJTRST: CN10.102 ; port NJTRST
NRST: CN10.17 ; port NRST
OTG_ID: CN9.98 ; port OTG_ID
OTG_VBUS: CN9.100 ; port OTG_VBUS
PA0_WKUP: CN10.15 ; port PA0_WKUP
PA13: CN9.25 ; port PA13
PA14: CN9.27 ; port PA14
PF12: CN9.57 SB20.2
QSPI_BK1_IO0: CN9.76
QSPI_BK1_IO1: CN9.78
QSPI_BK1_IO2: CN9.80
QSPI_BK1_IO3: CN9.82
QSPI_BK1_NCS: CN9.74 ; port QSPI_BK1_NCS
QSPI_BK2_IO0: CN9.64
QSPI_BK2_IO1: CN9.66
QSPI_BK2_IO2: CN9.68
QSPI_BK2_IO3: CN9.70
QSPI_BK2_NCS: CN9.72 ; port QSPI_BK2_NCS
QSPI_CLK: CN9.62 ; port QSPI_CLK
SAI2_FSA: CN10.112 SB11.1 SB63.2 SB65.2
SAI2_FSB: CN10.14 ; port SAI2_FSB
SAI2_MCLKA: CN10.110 SB7.1 SB53.2
SAI2_MCLKB: CN10.16 ; port SAI2_MCLKB
SAI2_SCKA: CN10.114 SB9.1 SB66.2 SB67.2
SAI2_SDA: CN10.118 SB10.1 SB73.2 SB75.2
SAI2_SDB: CN10.116 SB8.1 SB69.2 SB70.2
SDMMC3_CK: CN10.89 ; port EX_GPIO.SDMMC3_CK  [project net EXP_GPIO22]
SDMMC3_CMD: CN10.80 ; port EX_GPIO.SDMMC3_CMD  [project net EXP_GPIO23]
SDMMC3_D0: CN10.91 ; port EX_GPIO.SDMMC3_D0  [project net EXP_GPIO24]
SDMMC3_D1: CN10.87 ; port EX_GPIO.SDMMC3_D1  [project net EXP_GPIO25]
SDMMC3_D2: CN10.86 ; port EX_GPIO.SDMMC3_D2  [project net EXP_GPIO26]
SDMMC3_D3: CN10.88 ; port EX_GPIO.SDMMC3_D3  [project net EXP_GPIO27]
SmartCard_CLK: CN9.20 ; port SmartCard_CLK
SmartCard_IO: CN9.22 ; port SmartCard_IO
SPDIF_RX: CN10.120 ; port SPDIF_RX
SPDIF_TX: CN9.75 ; port SPDIF_TX  [project net SAI4_SD_A]
SPI1_MISO: CN10.84 ; port EX_GPIO.SPI1_MISO  [project net EXP_GPIO9]
SPI1_MOSI: CN10.82 ; port EX_GPIO.SPI1_MOSI  [project net EXP_GPIO10]
SPI1_NSS: CN10.85 ; port EX_GPIO.SPI1_NSS  [project net EXP_GPIO8]
SPI1_SCK: CN10.83 ; port EX_GPIO.SPI1_SCK  [project net EXP_GPIO11]
TIM2_CH4: CN9.37 SB14.2 SB15.2
TIM8_CH4: CN10.81 ; port EX_GPIO.TIM8_CH4  [project net EXP_GPIO13]
TIM12_CH1: CN9.77 SB27.2 SB29.2
TRACED0: SB43.2
TRACED1: SB42.2
TRACED2: SB36.2
TRACED3: SB41.2
TRACED4: SB40.2
TRACED5: SB39.2
TRACED6: SB49.2
TRACED7: SB35.2
TRACED8: SB34.2
TRACED9: SB37.2
TRACED10: SB48.2
TRACED11: SB47.2
TRACED12: SB46.2
TRACED13: SB45.2
TRACED14: SB44.2
TRACED15: SB50.2
UART4_RX: CN9.115 ; port UART4_RX
UART4_TX: CN9.113 ; port UART4_TX
USART3_CTS: CN9.31 ; port EX_GPIO.USART3_CTS  [project net EXP_GPIO16]
USART3_RX: CN9.71 ; port EX_GPIO.USART3_RX  [project net EXP_GPIO15]
USART3_TX: CN9.61 ; port EX_GPIO.USART3_TX  [project net EXP_GPIO14]
USB_AB_N: CN9.86 ; port USB_DM2
USB_AB_P: CN9.88 ; port USB_DP2
USB_HUB_N: CN9.94 ; port USB_DM1
USB_HUB_P: CN9.92 ; port USB_DP1
NetCN9_45: CN9.45 TP15.1
NetCN9_104: CN9.104 TP16.1
NetCN9_108: CN9.108 TP17.1
NetCN9_112: CN9.112 TP18.1
NetCN9_116: CN9.116 TP19.1
NetCN9_120: CN9.120 TP20.1
NetCN10_26: CN10.26 ; port SUB_NRST
NetCN13_1: SB54.2 ; port EXT_SDA
NetCN13_3: SB51.2 ; port EXT_SCL
NetR54_1: SB11.2 ; port SAI2_FSA
NetR77_1: SB77.2 ; port ETH_CLK
NetSB4_1: SB8.2 ; port SAI2_SDB
NetSB6_2: SB6.2 ; port SAI2_SCKB
NetSB7_2: SB7.2 ; port SAI2_MCLKA
NetSB9_2: SB9.2 ; port SAI2_SCKA
NetSB10_2: SB10.2 ; port SAI2_SDA
NetSB38_2: SB38.2 ; port TRACECLK

Not connected (* = marked no-connect by the designer): CN9 14* 16* 18* 35* 55* 67* 73* 83* 85* 102* 106* 110* 114* 117* 118* 119*; CN10 1* 3* 5* 6* 12* 13* 18* 19* 21* 22* 23* 25* 92* 94* 119*

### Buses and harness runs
bus DCMI_D[0..11] = port DCMI_D[0..11]
bus ETH_RXD[0..3] = port ETH_RXD[0..3]
bus ETH_TXD[0..3] = port ETH_TXD[0..3]
bus LTDC_B[0..7] = port LTDC_B[0..7]
bus LTDC_G[0..7] = port LTDC_G[0..7]
bus LTDC_R[0..7] = port LTDC_R[0..7]
bus NAND_D[0..7] = port NAND_D[0..7]
bus QSPI_BK1_IO[0..3] = port QSPI_BK1_IO[0..3]
bus QSPI_BK2_IO[0..3] = port QSPI_BK2_IO[0..3]
bus TRACED[0..15] = port TRACED[0..15]

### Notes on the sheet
- CAMERA
- JTAG
- QSPI
- NAND
- RGB LCD
- CAN TT&FD
- DSI LCD
- (near CN10) PA0
- (near CN10) PE13
- (near CN10) PE14
- (near CN10) PE15
- (near CN9) ANA1
- (near CN9) ANA0
- (near CN10) PD1
- (near CN10) PE12
- (near CN10) PE11
- (near CN10) PD6
- (near CN10) PD10
- (near CN10) PD5
- (near CN9) PA13
- (near CN9) PA14
- (near CN9) PE2
- (near CN9) PZ7
- (near CN9) PZ6
- (near CN9) PC3
- (near CN10) PD0
- (near CN10) PI12
- (near CN10) PJ3
- (near CN10) PJ9
- (near CN10) PD4
- (near CN10) PI13
- (near CN10) PI14
- (near CN10) PJ5
- (near CN9) PI8
- (near CN9) PI10
- (near CN9) PI11
- (near CN9) PA3
- (near CN9) PC1
- (near CN9) PA2
- (near CN9) PG13
- (near CN9) PG14
- (near CN9) PC2
- (near CN10) PJ0
- (near CN10) PJ8
- (near CN10) PJ7
- (near CN10) PJ6
- (near CN10) PI15
- (near CN10) PJ4
- (near CN10) PJ10
- (near CN10) PJ2
- (near CN10) PJ1
- (near CN10) PJ11
- (near CN9) PG3
- (near CN9) PF3
- (near CN9) PG2
- (near CN9) PG1
- (near CN9) PG0
- (near CN9) PA1
- (near CN9) PG4
- (near CN10) PK7
- (near CN10) PK3
- (near CN10) PK5
- (near CN10) PJ15
- (near CN10) PJ12
- (near CN10) PK6
- (near CN10) PK4
- (near CN10) PJ13
- (near CN10) PJ14
- (near CN10) PK1
- (near CN9) PG5
- (near CN9) PF12
- (near CN9) PC4
- (near CN9) PC5
- (near CN9) PB0
- (near CN9) PB1
- (near CN9) PB11
- (near CN10) PK2
- (near CN10) PH14
- (near CN10) PI3
- (near CN10) PH7
- (near CN10) PK0
- (near CN10) PI1
- (near CN10) PH12
- (near CN10) PI4
- (near CN9) PF15
- (near CN9) PB10
- (near CN9) PB13
- (near CN9) PF13
- (near CN9) PH3
- (near CN9) PH2
- (near CN9) PF10
- (near CN9) PA7
- (near CN10) PA6
- (near CN10) PB8
- (near CN10) PH10
- (near CN10) PH11
- (near CN10) PH15
- (near CN10) PH9
- (near CN10) PH8
- (near CN10) PE6
- (near CN10) PB7
- (near CN9) PG8
- (near CN9) PB12
- (near CN9) PB5
- (near CN9) PF8
- (near CN9) PB6
- (near CN9) PC0
- (near CN9) PG7
- (near CN9) PG10
- (near CN10) PH4
- (near CN10) PI2
- (near CN10) PZ0
- (near CN10) PZ3
- (near CN10) PH5
- (near CN10) PF1
- (near CN10) PZ2
- (near CN10) PZ1
- (near CN10) PF5
- (near CN9) PH6
- (near CN9) PD15
- (near CN9) PD8
- (near CN9) PD9
- (near CN9) PF6
- (near CN9) PF7
- (near CN9) PF9
- (near CN10) PF4
- (near CN10) PG15
- (near CN10) PF0
- (near CN10) PA15
- (near CN10) PH13
- (near CN10) PD7
- (near CN10) PI0
- (near CN10) PE1
- (near CN9) PD14
- (near CN9) PD11
- (near CN9) PE7
- (near CN9) PE9
- (near CN9) PE8
- (near CN10) PI9
- (near CN9) PD12
- (near CN9) PA11
- (near CN9) PG9
- (near CN9) PE10
- PA10
- (near CN10) PE0
- (near CN10) PI7
- (near CN10) PI5
- (near CN10) PF11
- (near CN9) PA12
- (near CN9) PD13
- (near CN9) PG11
- (near CN9) PB2
- (near CN10) PC6
- (near CN10) PI6
- (near CN10) PG12
- MOTOR CONTROL
- AUDIO
- (near SB77) ETHERNET

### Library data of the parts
CN9 CN10 = QSH-060-01-L-D-A: Samtec connector QSH 120p; Fitted: YES; Ordered_By: Subcon
SB1 SB12-SB14 SB19-SB24 SB26 SB28-SB30 SB32 SB33 SB52 SB53 SB55 SB63 SB65-SB67 SB69 SB70 SB72-SB76 = SB_OFF: Solder Bridge OFF; Fitted: NO; Ordered_By: Subcon; Solder: NO
SB6-SB11 SB15 SB17 SB27 SB34-SB51 SB54 SB77 = SB_ON: Solder Bridge ON; Fitted: YES; Ordered_by: Subcon
TP15-TP20 = TP 1mm: as TP21-TP23 on sheet MFX

## Sheet SmartCard.SchDoc: SmartCard
size A4; DocumentNumber: MB1262; Revision: C-01; SheetNumber: 13; SheetTotal: 17; Project: STM32MP15x-EVAL
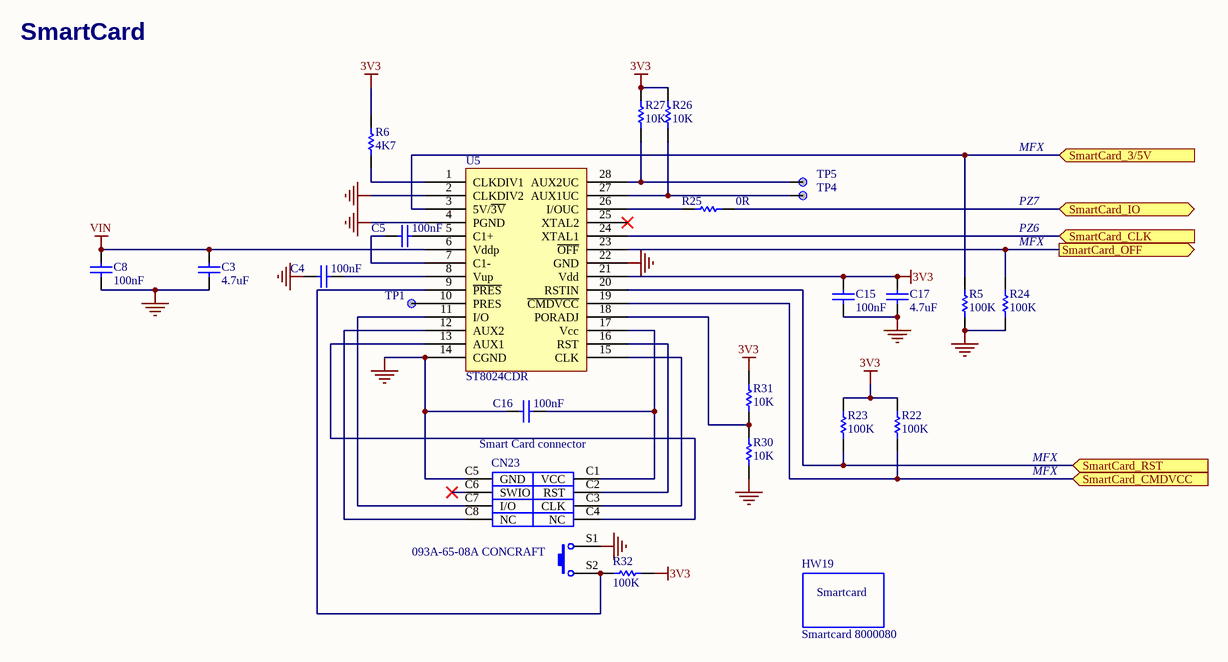
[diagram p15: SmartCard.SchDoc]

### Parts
C3  4.7uF  [C0402]
C4  100nF  [C0402]
C5  100nF  [C0402]
C8  100nF  [C0402]
C15  100nF  [C0402]
C16  100nF  [C0402]
C17  4.7uF  [C0402]
CN23  093A-65-08A CONCRAFT  [CON_SMARTCARD_CONCRAFT_093A-65-08A]
HW19  Smartcard 8000080
R5  100K  [R0402]
R6  4K7  [R0402]
R22  100K  [R0402]
R23  100K  [R0402]
R24  100K  [R0402]
R25  0R  [R0402]
R26  10K  [R0402]
R27  10K  [R0402]
R30  10K  [R0402]
R31  10K  [R0402]
R32  100K  [R0402]
TP1  TP  [TP_SMD_1MM]  (value not drawn)
TP4  TP  [TP_SMD_1MM]  (value not drawn)
TP5  TP  [TP_SMD_1MM]  (value not drawn)
U5  ST8024CDR  [ICC_SO28_18P10X7P60_P127]

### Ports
SmartCard_3/5V (in), SmartCard_CLK (in), SmartCard_CMDVCC (in), SmartCard_IO (bidir), SmartCard_OFF (out), SmartCard_RST (in)

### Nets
3V3: C15.1 C17.2 R6.2 R22.2 R23.2 R26.2 R27.2 R31.2 R32.1 U5.21(Vdd)
GND: C3.1 C4.2 C8.1 C15.2 C16.2 C17.1 CN23.C5(GND) CN23.S1 R5.1 R24.1 R30.1 U5.2(CLKDIV2) U5.4(PGND) U5.14(CGND) U5.22(GND)
VIN: C3.2 C8.2 U5.6(Vddp)
SmartCard_CLK: U5.24(XTAL1) ; port SmartCard_CLK
SmartCard_IO: R25.2 ; port SmartCard_IO
NetC4_1: C4.1 U5.8(Vup)
NetC5_1: C5.1 U5.5(C1+)
NetC5_2: C5.2 U5.7(C1-)
NetC16_1: C16.1 CN23.C1(VCC) U5.17(Vcc)
NetCN23_C2: CN23.C2(RST) U5.16(RST)
NetCN23_C3: CN23.C3(CLK) U5.15(CLK)
NetCN23_C4: CN23.C4(NC) U5.13(AUX1)
NetCN23_C7: CN23.C7(I/O) U5.11(I/O)
NetCN23_C8: CN23.C8(NC) U5.12(AUX2)
NetCN23_S2: CN23.S2 R32.2 U5.9(~{PRES})
NetR5_2: R5.2 U5.3(5V/~{3V}) ; port SmartCard_3/5V
NetR6_1: R6.1 U5.1(CLKDIV1)
NetR22_1: R22.1 U5.19(~{CMDVCC}) ; port SmartCard_CMDVCC
NetR23_1: R23.1 U5.20(RSTIN) ; port SmartCard_RST
NetR24_2: R24.2 U5.23(~{OFF}) ; port SmartCard_OFF
NetR25_1: R25.1 U5.26(I/OUC)
NetR26_1: R26.1 TP4.1 U5.27(AUX1UC)
NetR27_1: R27.1 TP5.1 U5.28(AUX2UC)
NetR30_2: R30.2 R31.1 U5.18(PORADJ)
NetTP1_1: TP1.1 U5.10(PRES)

Not connected (* = marked no-connect by the designer): CN23 C6(SWIO)*; U5 25(XTAL2)*

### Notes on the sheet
- SmartCard
- MFX
- PZ6
- PZ7
- Smart Card connector

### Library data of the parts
C3 C17 = Cap_4.7uF_X5R_20%_6V3_0402: Capacitor MLCC 4,7µF 20% 6,3V 1,9uF@3,3V X5R 0402; Manuf_Part_1: GRM155R60J475ME87; Manuf_1: MURATA; Fitted: YES; Ordered_By: Subcon
C4 C5 C8 C15 C16 = Cap_100nF_X7R_10%_0402: as C119 on sheet Peripherals
CN23 = Smart_card_CN: Smartcard connector; Comments: Smartcard "GSM file and SWP" connector; ECCN_US/EU: NA; Assembly: with ST smartcard 8000080; Ordered_By: Subcon; Fitted: YES
HW19 = Smartcard: Ordered_By: STM; ECCN_US/EU: NA; Assembly: with smart card connector; Fitted: NO
R5 R22-R24 R32 = Res_100K_1%_0402: as R135 on sheet MotorControl
R6 = Res_4K7_1%_0402: Resistor,4K7,0402,1%,YAGEO; Manuf_Part_2: RT0402FRE074K7L; Manuf_Part_1: RC0402FR-074K7L; Fitted: YES; Ordered_By: Subcon
R25 = Res_0_5%_0402: as R103 on sheet Peripherals
R26 R27 R30 R31 = Res_10K_1%_0402: as R101 on sheet Peripherals
TP1 TP4 TP5 = TP 1mm: as TP21-TP23 on sheet MFX
U5 = ST8024CDR: Smartcard interface; Manuf_1: ST; Ordered_By: Subcon; ECCN_US/EU: EAR99/NEC; Ref St: 9177802; Fitted: YES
